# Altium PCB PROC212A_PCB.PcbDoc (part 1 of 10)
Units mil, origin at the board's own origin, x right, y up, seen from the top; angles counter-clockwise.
Board outline 3032.48 x 3598.78 mil, 4 copper layers (Top Layer, L2_GND1, L3_PWR1, Bottom Layer), stack 60.58 mil thick; 432 components, 310 nets, 7775 pads, 1236 vias.
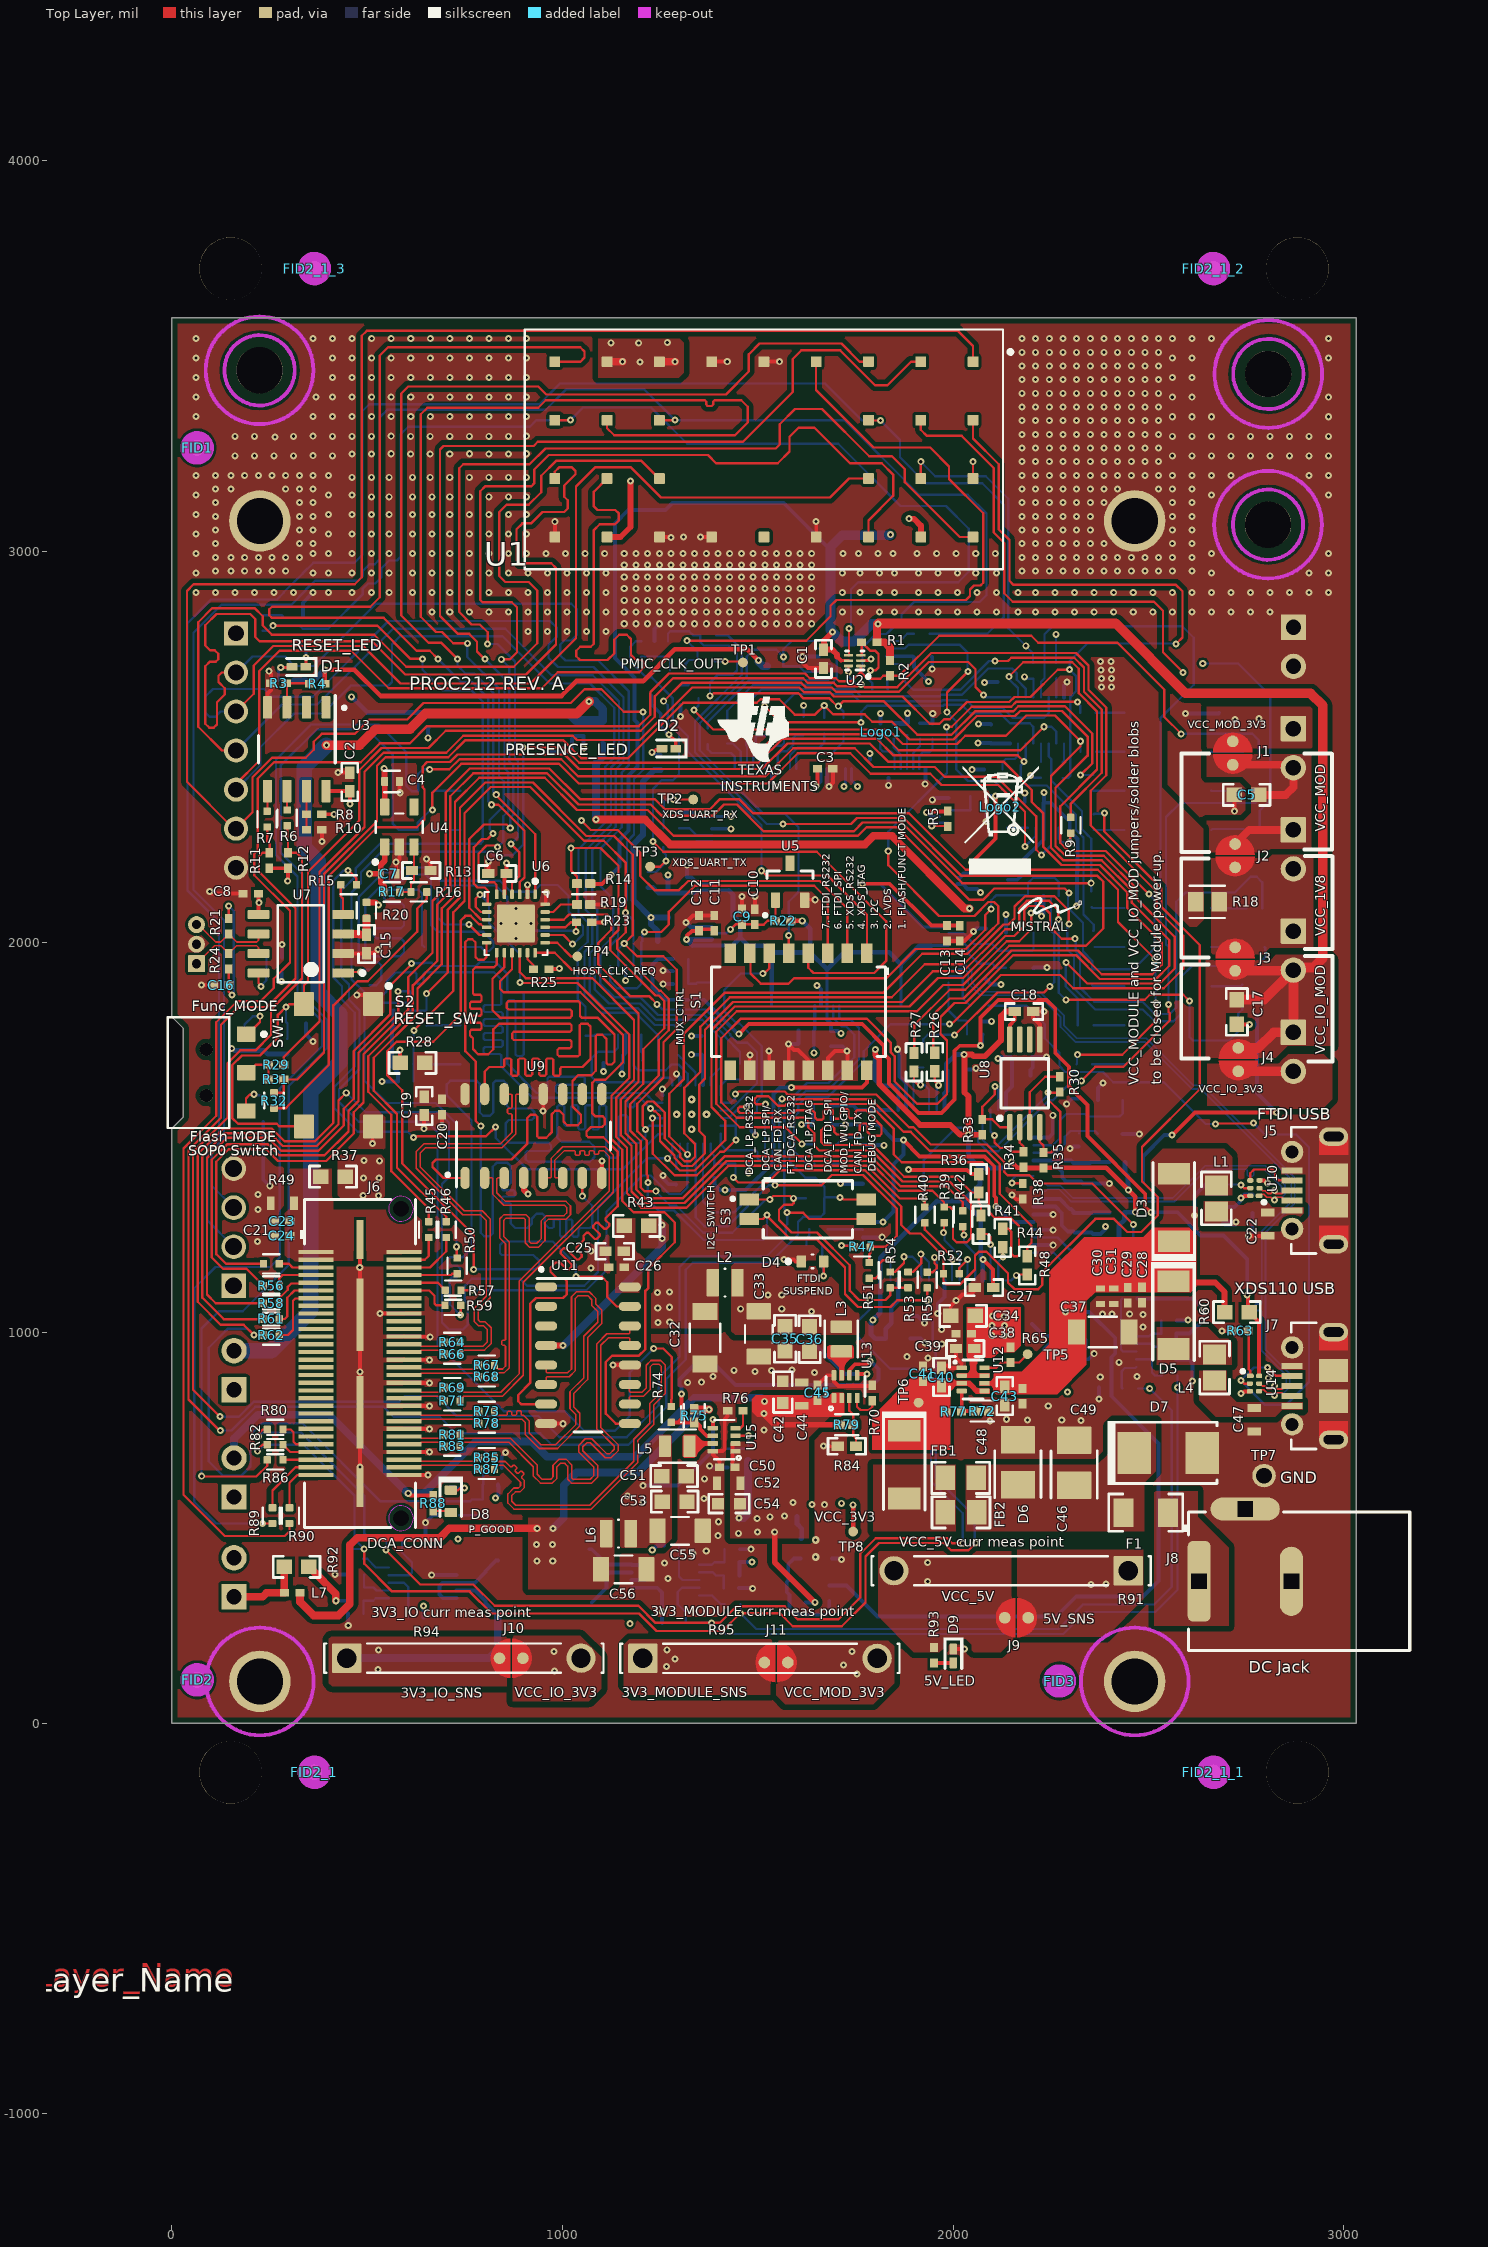
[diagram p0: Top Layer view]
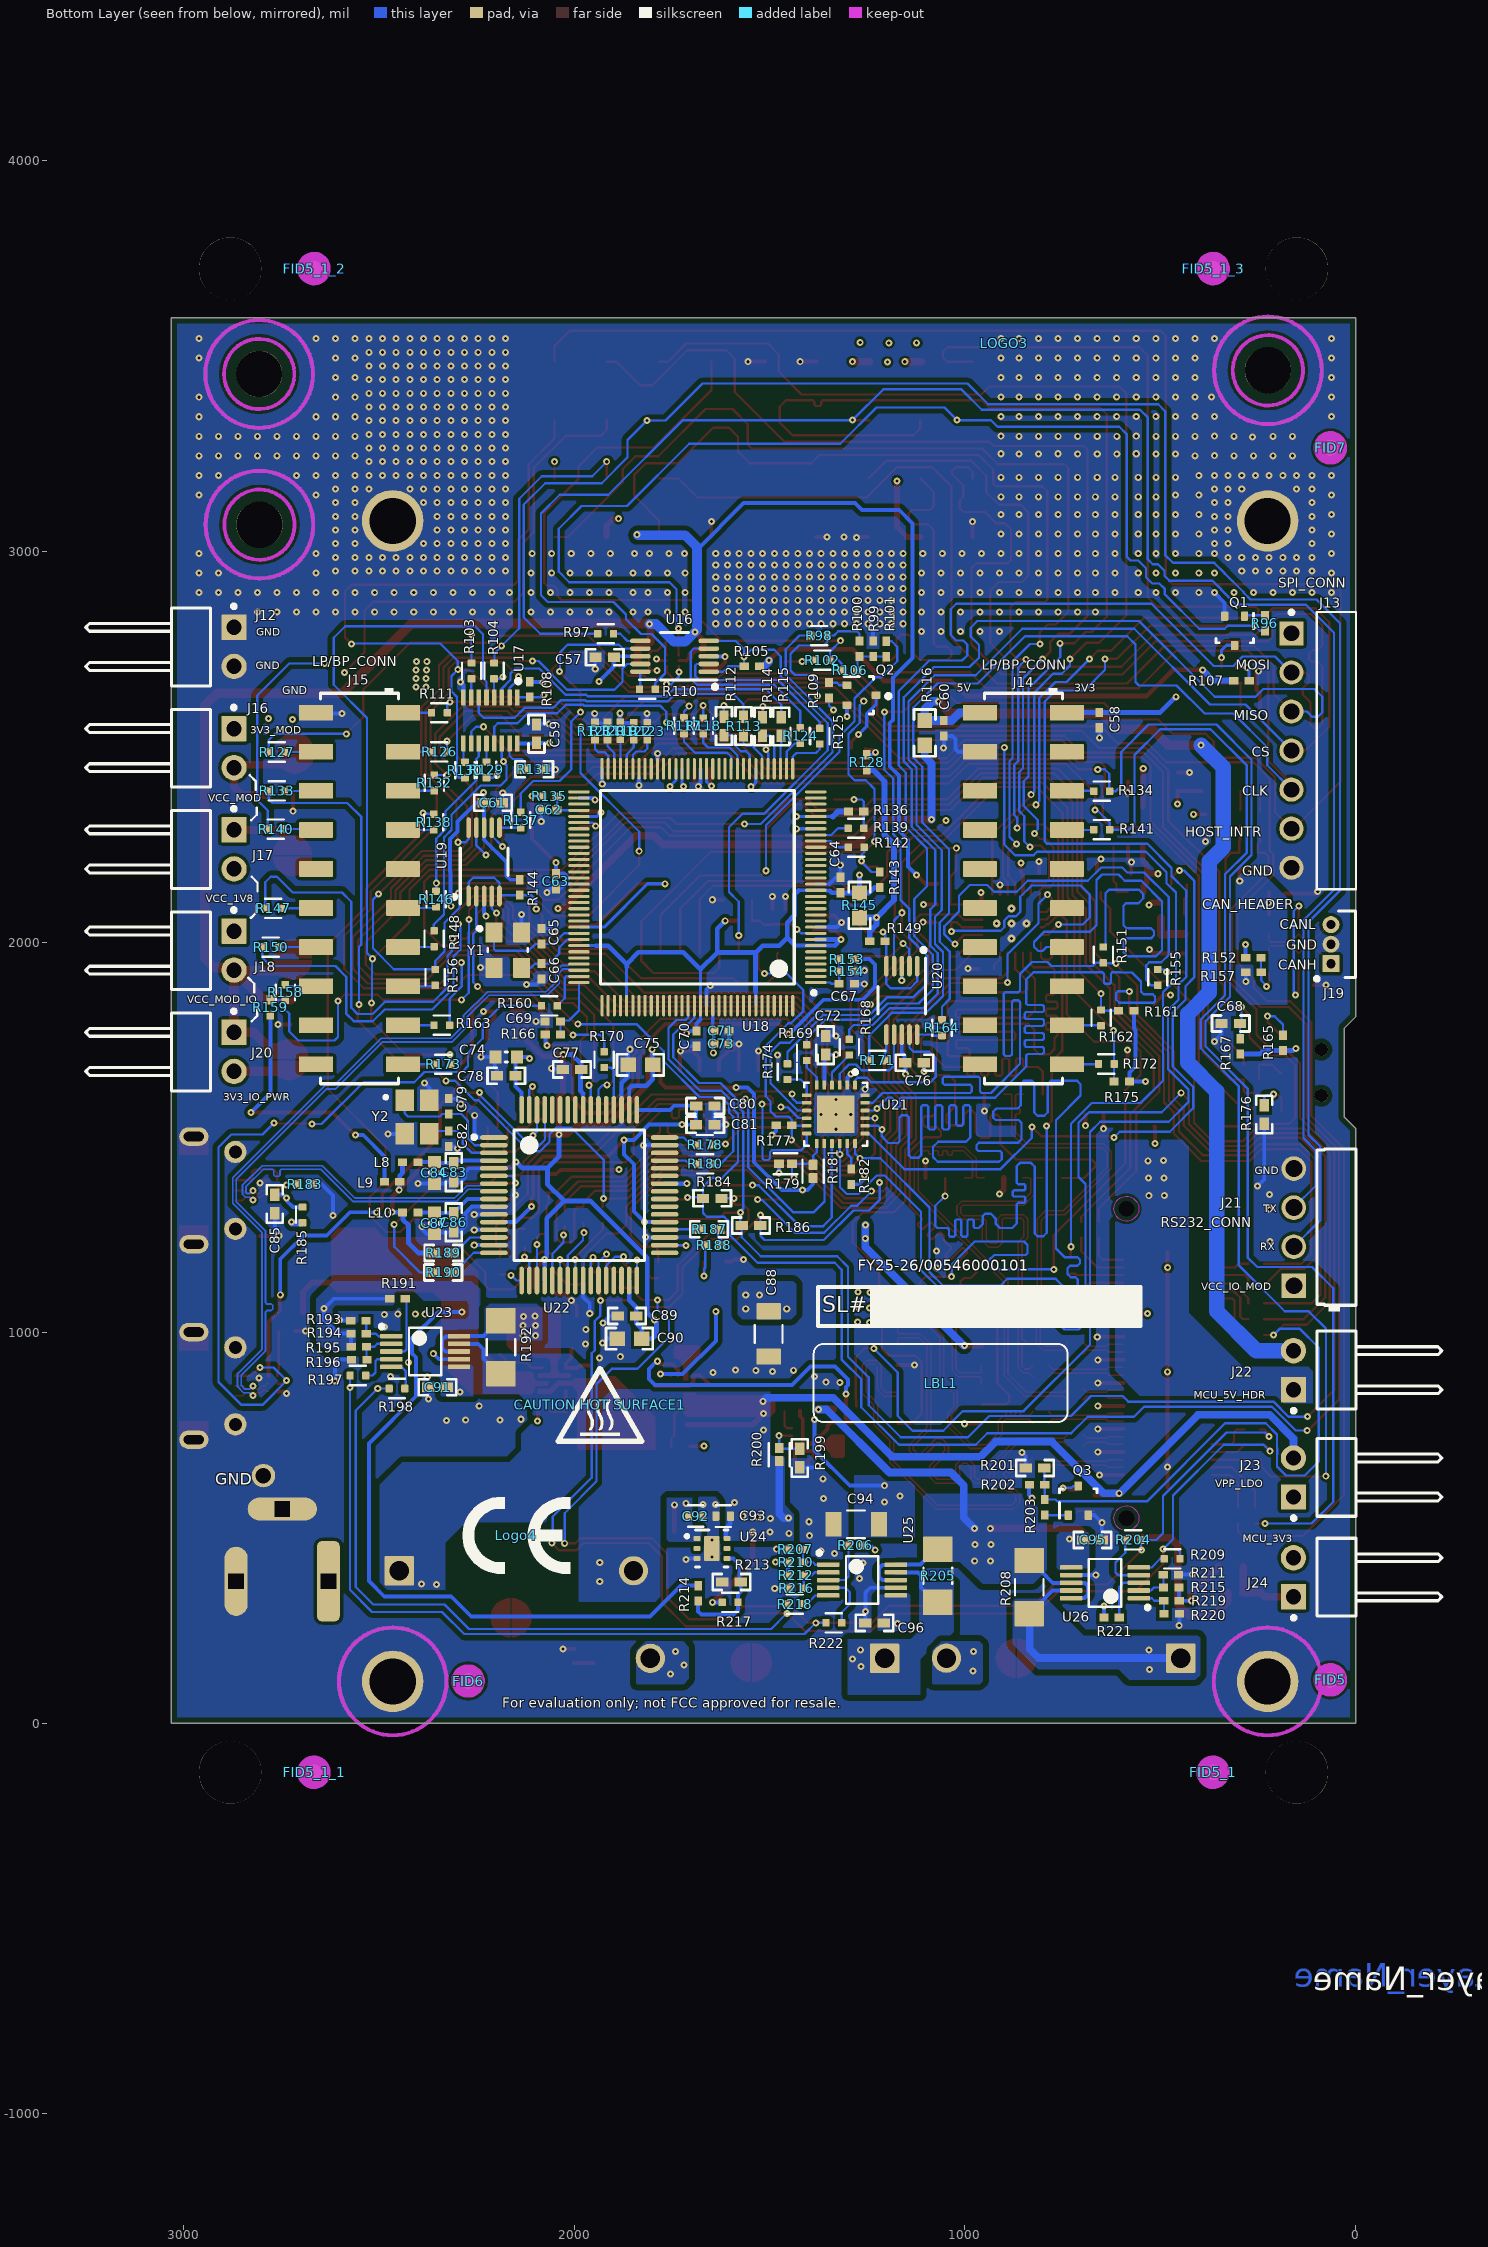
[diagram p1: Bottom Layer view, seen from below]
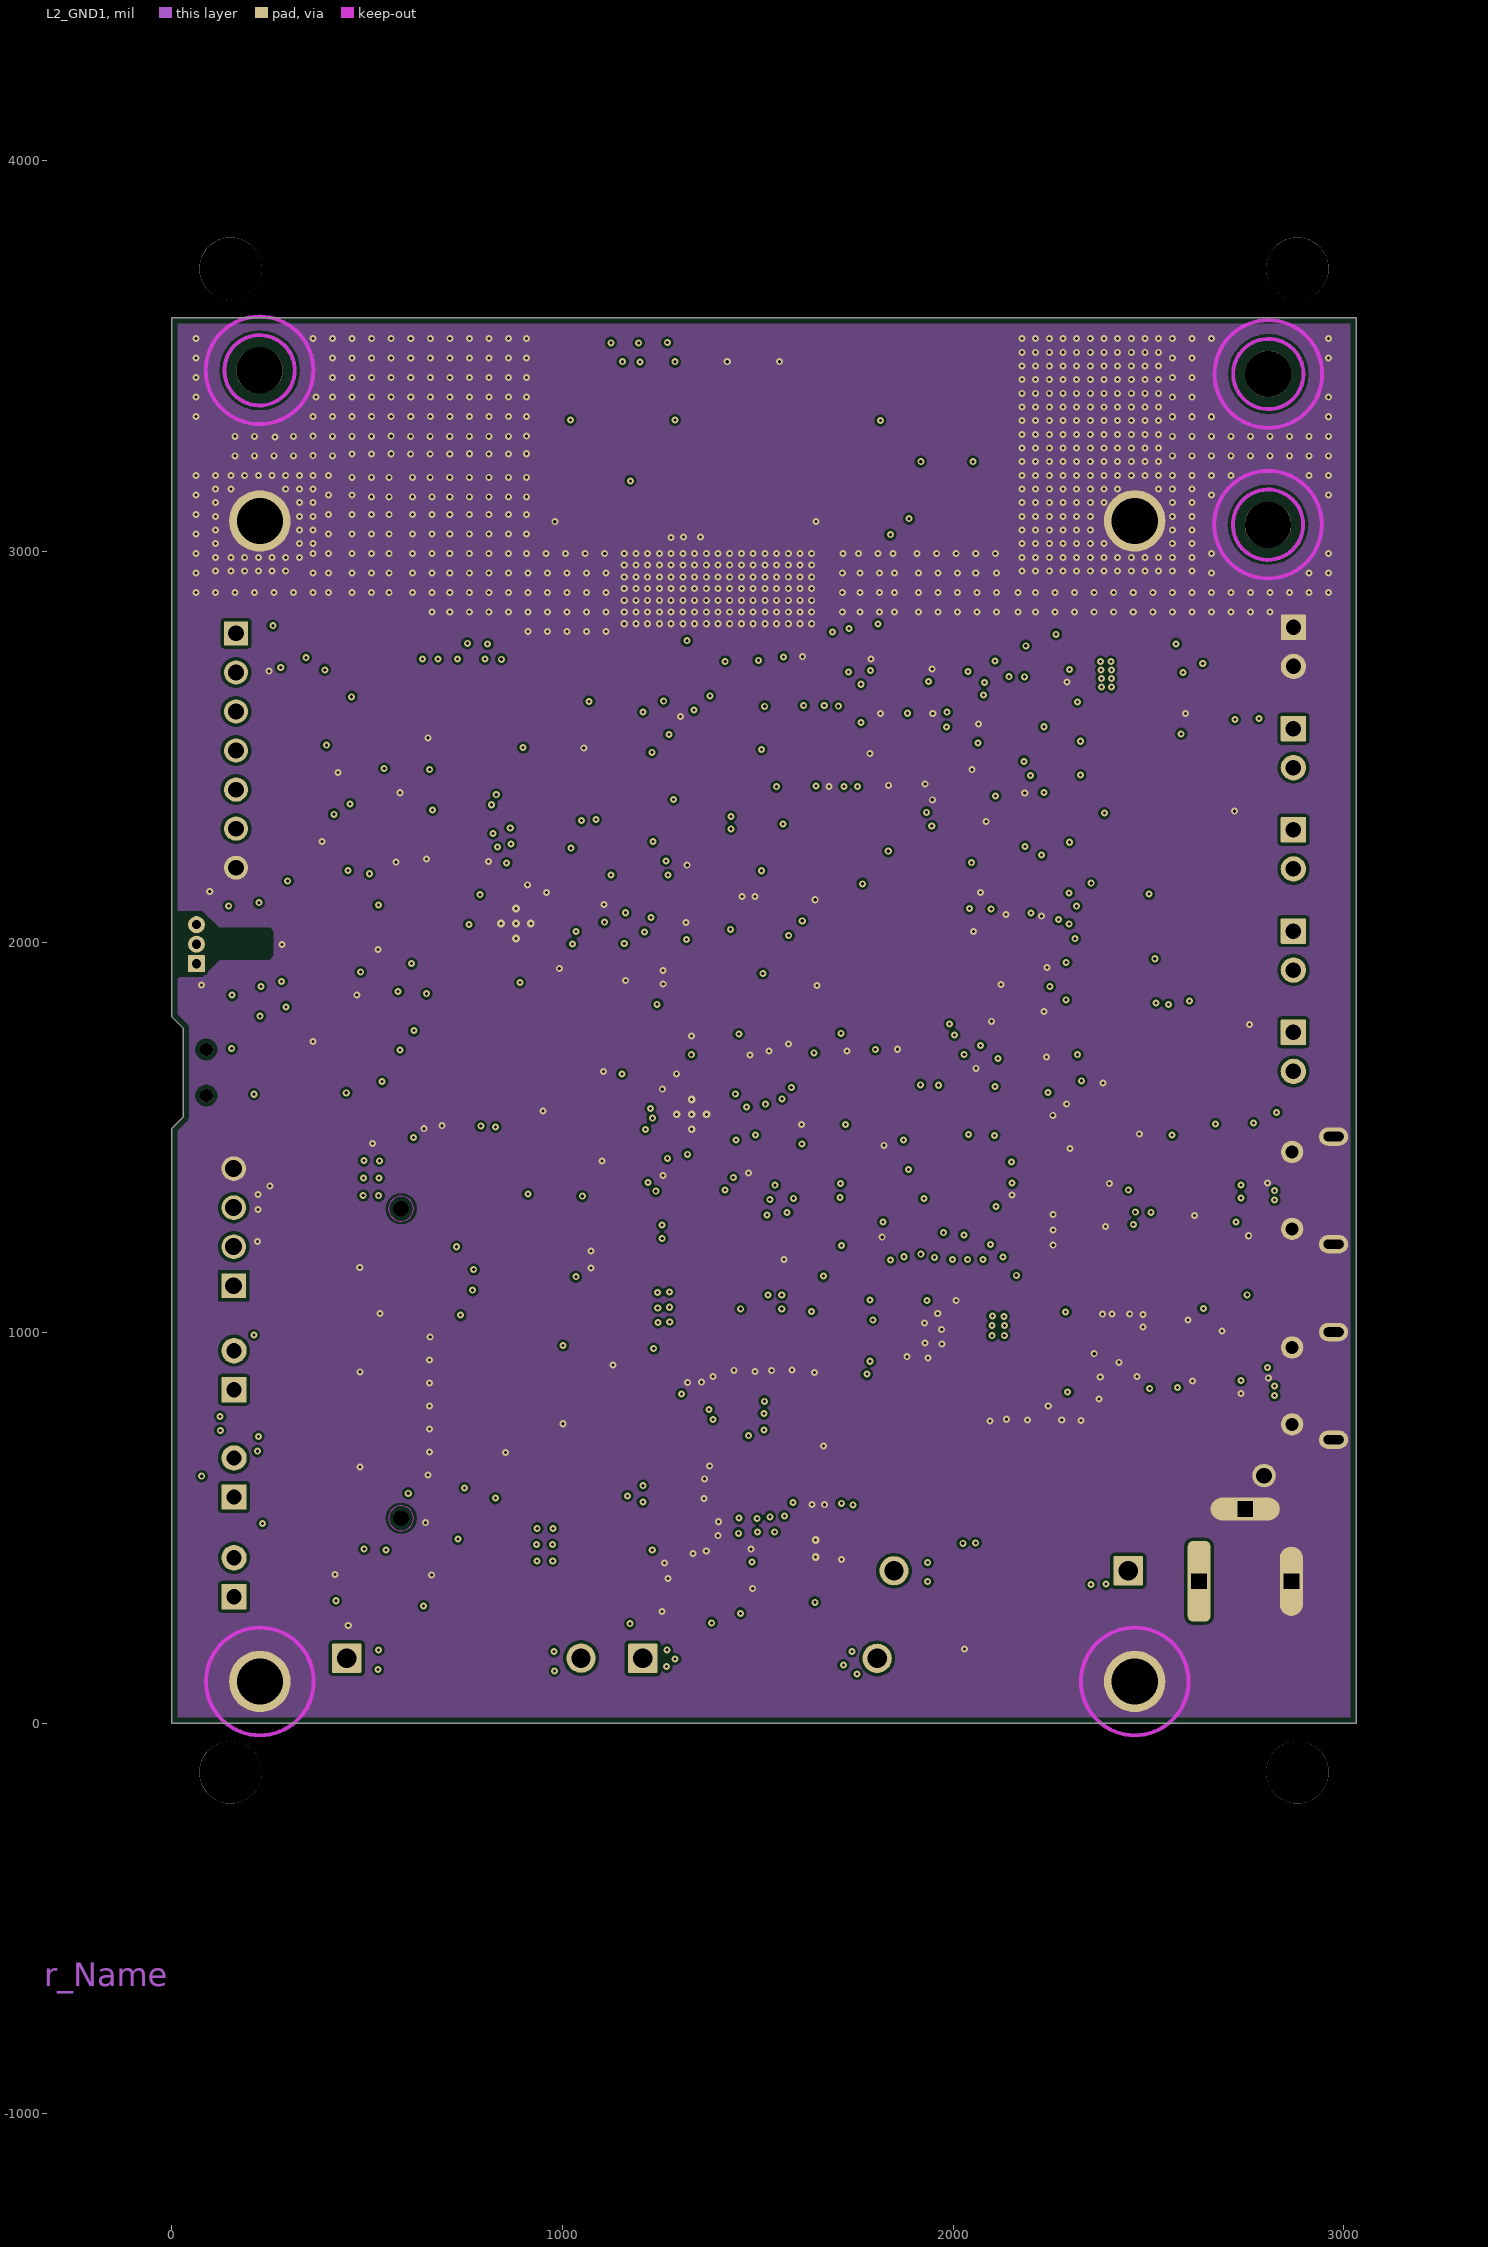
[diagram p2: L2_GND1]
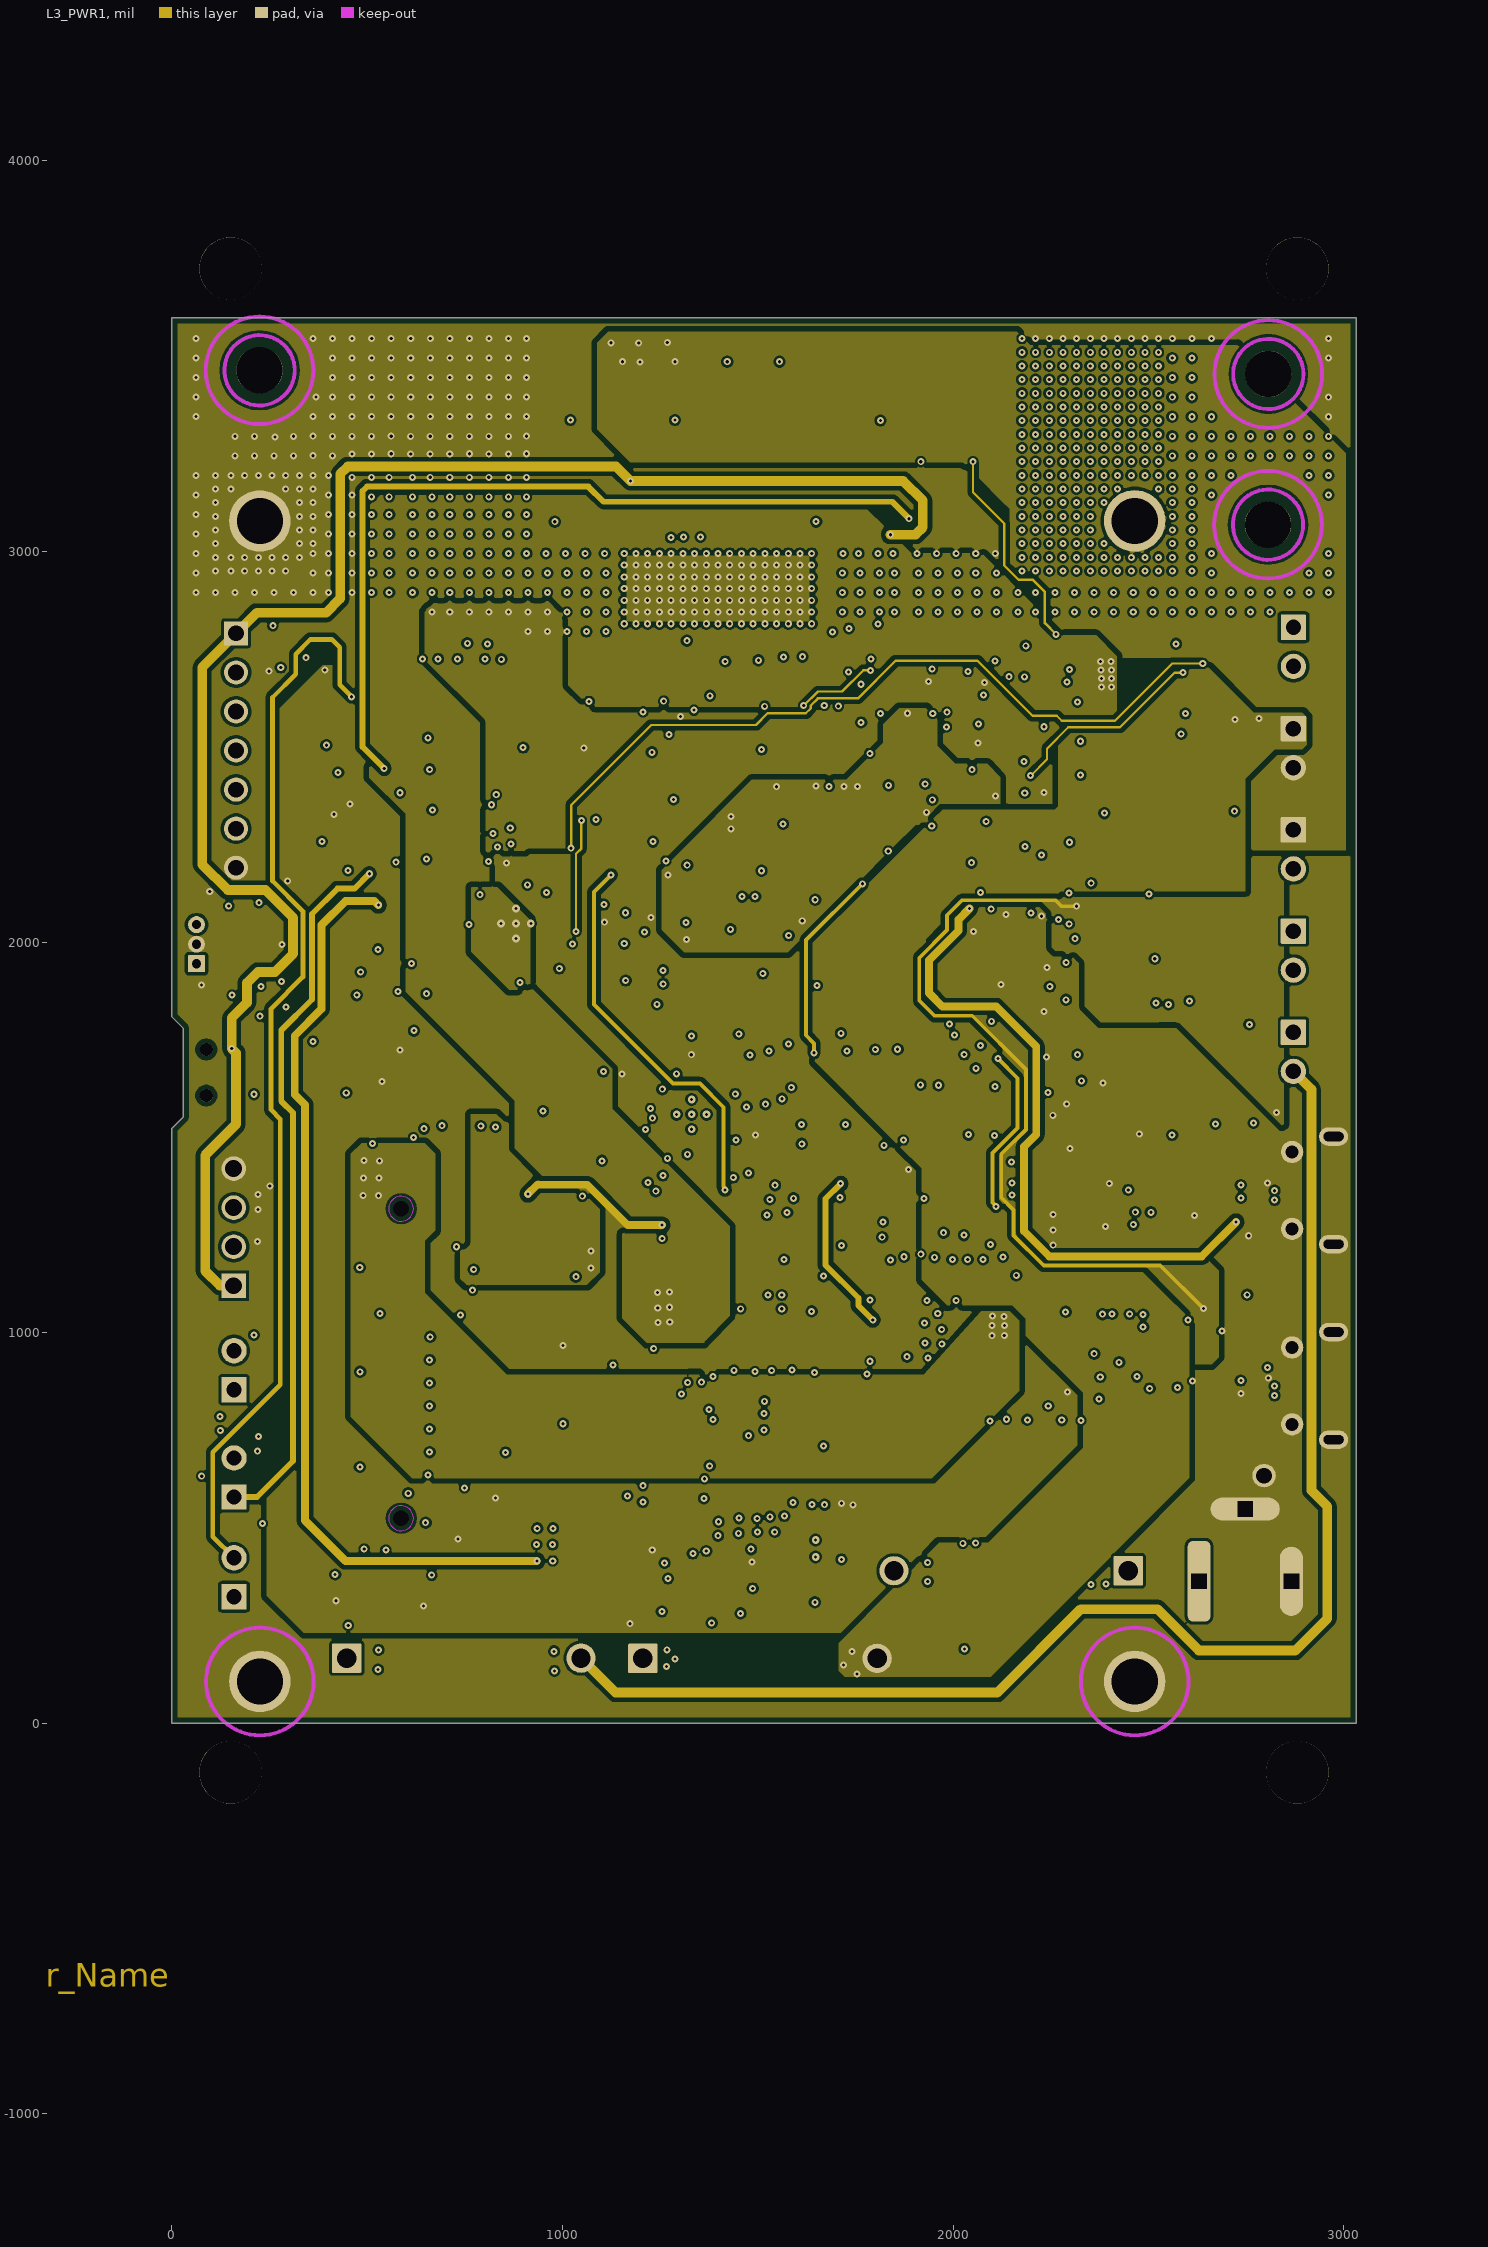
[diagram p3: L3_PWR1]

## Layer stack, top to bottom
Top Solder: solder mask 1, Solder Resist, Dk 3.5
Top Layer: signal copper 1.85
Dielectric 1: prepreg 1.779, Iteq IT180A Prepreg 106 RC71-NEW, Dk 3.79
Dielectric 2: prepreg 1.779, Iteq IT180A Prepreg 106 RC71-NEW, Dk 3.79
L2_GND1: signal copper 1.26
Dielectric 3: core 47.244, Iteq IT180A 50 mil core 1/1, Dk 4.28
L3_PWR1: signal copper 1.26
Dielectric 4: prepreg 1.779, Iteq IT180A Prepreg 106 RC71-NEW, Dk 3.79
Dielectric 5: prepreg 1.779, Iteq IT180A Prepreg 106 RC71-NEW, Dk 3.79
Bottom Layer: signal copper 1.85
Bottom Solder: solder mask 1, Solder Resist, Dk 3.5

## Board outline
0,0 0,1523.4 29.41,1552.81 29.41,1779.02 0,1808.43 0,3598.78 3031.47,3598.78 3032.48,3598.78 3032.48,0

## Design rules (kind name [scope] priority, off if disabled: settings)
AcuteAngle [All] p1 off: minimum=4.50000000000000E+0001 checktracksonly=FALSE
AssemblyTestPointUsage [All] p1: valid=2
BoardOutlineClearance BoardOutlineClearance_Silkoultine [OnBottomSilkscreen] p1: gap=12 ignorepadtopadclearanceinfootprint=FALSE except(0: Track-OutlineEdge Text-OutlineEdge; 15: Poly-OutlineEdge)
BoardOutlineClearance BoardOutlineClearance_J8 [InComponent('J8')] p2: gap=12 ignorepadtopadclearanceinfootprint=FALSE except(0: Track-OutlineEdge Text-OutlineEdge)
BoardOutlineClearance BoardOutlineClearance_SW1 [InComponent('SW1')] p3: gap=12 ignorepadtopadclearanceinfootprint=FALSE except(0: Track-OutlineEdge Text-OutlineEdge)
BoardOutlineClearance BoardOutlineClearance_Text [OnBottomSilkscreen] p4: gap=12 ignorepadtopadclearanceinfootprint=FALSE except(0: Track-OutlineEdge Text-OutlineEdge)
BoardOutlineClearance [All] p5: gap=12 ignorepadtopadclearanceinfootprint=FALSE except(15: Poly-OutlineEdge)
Clearance SOLDER_JUMPER [HasFootprint('SolderJumper')] p1: gap=6 ignorepadtopadclearanceinfootprint=TRUE except(0: Text-Hole; 4.8: SMDPad-Region Region-Region; 5: Arc-Arc Arc-Track Arc-SMDPad Track-SMDPad; 5.1: SMDPad-SMDPad; 7: Arc-Fill Arc-Poly Arc-Region Track-Fill Track-Region Poly-Region; 8: SMDPad-Fill SMDPad-Poly THPad-Fill THPad-Poly THPad-Region; 10: Fill-Fill Fill-Poly Fill-Region; 11: Fill-Hole Poly-Hole Region-Hole; 12: Track-Poly; 15: Poly-Poly)
Clearance 120E_Clearance [InNetClass('120E')] p2: gap=6 ignorepadtopadclearanceinfootprint=TRUE except(0: Text-Hole; 5: Arc-Arc Arc-Track Arc-SMDPad Track-SMDPad; 5.1: Track-Track SMDPad-SMDPad; 7: Arc-Fill Arc-Poly Arc-Region Track-Region SMDPad-Region; 8: SMDPad-Fill SMDPad-Poly THPad-Fill THPad-Poly THPad-Region; 10: Fill-Fill Fill-Poly Fill-Region Poly-Region Region-Region; 11: Fill-Hole Poly-Hole Region-Hole; 12: Track-Fill Track-Poly; 15: Poly-Poly)
Clearance 90E_1 [InNetClass('90E')] p3: gap=6 ignorepadtopadclearanceinfootprint=TRUE except(0: Text-Hole; 4.5: Track-Track Track-Via; 5: Arc-Arc Arc-Track Arc-SMDPad Track-SMDPad; 5.1: SMDPad-SMDPad; 7: Arc-Fill Arc-Poly Arc-Region Track-Fill Track-Region SMDPad-Region; 8: SMDPad-Fill SMDPad-Poly THPad-Fill THPad-Poly THPad-Region; 10: Fill-Fill Fill-Poly Fill-Region Poly-Region Region-Region; 11: Fill-Hole Poly-Hole Region-Hole; 12: Track-Poly; 15: Poly-Poly)
Clearance [All] p4: gap=6 ignorepadtopadclearanceinfootprint=TRUE except(0: Text-Hole; 5: Arc-Arc Arc-Track Arc-SMDPad Track-SMDPad; 5.1: SMDPad-SMDPad; 7: Arc-Fill Arc-Poly Arc-Region Track-Fill Track-Region SMDPad-Region Region-Region; 8: SMDPad-Fill SMDPad-Poly THPad-Fill THPad-Poly THPad-Region; 10: Fill-Fill Fill-Poly Fill-Region Poly-Region; 11: Fill-Hole Poly-Hole Region-Hole; 12: Track-Poly; 15: Poly-Poly)
Clearance Clearance_Keepout [IsKeepOut] p5: gap=0 ignorepadtopadclearanceinfootprint=TRUE
Clearance Clearance_BGA [WithinRoom('BGA1')] p6: gap=4 ignorepadtopadclearanceinfootprint=FALSE except(8: Fill-Fill Fill-Poly Fill-Region Poly-Poly Poly-Region Region-Region; 10: Fill-Hole Poly-Hole Region-Hole)
Clearance "top and bottom" [OnTopLayer or OnBottomLayer] p7: gap=6 ignorepadtopadclearanceinfootprint=TRUE except(5: Arc-Arc Arc-Track Arc-SMDPad Arc-Hole Track-Track Track-SMDPad Track-Hole SMDPad-Hole THPad-Hole Via-Hole Text-Hole; 5.1: SMDPad-SMDPad; 7: Arc-Fill Arc-Poly Arc-Region Track-Fill Track-Region; 8: Track-Poly SMDPad-Fill SMDPad-Poly SMDPad-Region THPad-Fill THPad-Poly THPad-Region Via-Fill Via-Poly Via-Region Poly-Poly; 10: Fill-Fill Fill-Poly Fill-Region Poly-Region Region-Region; 11: Fill-Hole Poly-Hole Region-Hole)
Clearance "Inner layers" [OnLayer('L3_SIGNAL 1') OR ('L6_SIGNAL 4')] p8: gap=6 ignorepadtopadclearanceinfootprint=TRUE except(0: Text-Hole; 5: Arc-Arc Arc-Track Arc-SMDPad Track-SMDPad; 5.1: SMDPad-SMDPad; 7: Arc-Fill Arc-Poly Arc-Region Track-Fill Track-Region; 8: SMDPad-Fill SMDPad-Poly SMDPad-Region THPad-Fill THPad-Poly THPad-Region; 10: Fill-Fill Fill-Poly Fill-Region Poly-Region Region-Region; 11: Fill-Hole Poly-Hole Region-Hole; 15: Track-Poly; 20: Poly-Poly)
Clearance Same_net [All] p9: gap=0 ignorepadtopadclearanceinfootprint=TRUE
Clearance Fiducial [HasFootprint('Fiducial10-20')] p10: gap=0 ignorepadtopadclearanceinfootprint=TRUE
ComponentClearance ComponentClearance_MatingCon-3D [All vs InComponentClass('Header')] p1: gap=0 collisioncheckmode=3 verticalgap=100 showdistances=FALSE
ComponentClearance "ComponentClearance_WEE Logo" [InComponent('Logo4')] p2: gap=0 collisioncheckmode=3 verticalgap=0 showdistances=TRUE
ComponentClearance ComponentClearance_Logo [InComponentClass('Logo')] p3: gap=0 collisioncheckmode=3 verticalgap=0 showdistances=TRUE
ComponentClearance "ComponentClearance_Mounting Holes_Fiducial Marks" [InComponentClass('FiducialMark') vs InPadClass('Mounting Holes PADS')] p4: gap=50 collisioncheckmode=3 verticalgap=10 showdistances=TRUE
ComponentClearance [All] p5: gap=6 collisioncheckmode=3 verticalgap=10 showdistances=TRUE
DiffPairsRouting 90E [InDifferentialPairClass('90E')] p1: maxlimit=4.5 minlimit=4.5 mostfreqgap=4.5 toplayer_minwidth=4.5 toplayer_maxwidth=4.5 toplayer_prefwidth=4.5 midlayer1_minwidth=4.5 midlayer1_maxwidth=4.5 midlayer1_prefwidth=4.5 midlayer5_minwidth=4.5 midlayer5_maxwidth=4.5 midlayer5_prefwidth=4.5 bottomlayer_minwidth=4.5 bottomlayer_maxwidth=4.5 bottomlayer_prefwidth=4.5 maxuncoupledlength=500
DiffPairsRouting 100E [InDifferentialPairClass('100E')] p2: maxlimit=6 minlimit=6 mostfreqgap=6 toplayer_minwidth=4 toplayer_maxwidth=4 toplayer_prefwidth=4 midlayer1_minwidth=4 midlayer1_maxwidth=4 midlayer1_prefwidth=4 midlayer5_minwidth=4 midlayer5_maxwidth=4 midlayer5_prefwidth=4 bottomlayer_minwidth=4 bottomlayer_maxwidth=4 bottomlayer_prefwidth=4 maxuncoupledlength=500
DiffPairsRouting 120E [InDifferentialPair('CAN')] p3: maxlimit=5.1 minlimit=5.1 mostfreqgap=5.1 toplayer_minwidth=4 toplayer_maxwidth=4 toplayer_prefwidth=4 midlayer1_minwidth=4 midlayer1_maxwidth=4 midlayer1_prefwidth=4 midlayer5_minwidth=4 midlayer5_maxwidth=4 midlayer5_prefwidth=4 bottomlayer_minwidth=4 bottomlayer_maxwidth=4 bottomlayer_prefwidth=4 maxuncoupledlength=500
FabricationTestPointUsage TestPointUsage [All] p1: valid=2 allowmultiple=FALSE
FabricationTestpoint Testpoint [All] p1: side=3 testpointundercomponent=TRUE minsize=40 maxsize=100 preferedsize=60 minholesize=0 maxholesize=40 preferedholesize=32 testpointgrid=1 allowsidetop=TRUE allowsidebottom=TRUE usegrid=TRUE gridtolerance=0.01
FanoutControl Fanout_LCC [IsLCC] p1: bgadir=Out bgaviamode=Centered fanoutstyle=Auto fanoutdirection=Alternating viagrid=1 // Fanout_LCC (Default Rule)
FanoutControl Fanout_BGA [IsBGA] p2: bgadir=Out bgaviamode=Centered fanoutstyle=Auto fanoutdirection=Alternating viagrid=1 // Fanout_BGA (Default Rule)
FanoutControl Fanout_Default [All] p4: bgadir=Out bgaviamode=Centered fanoutstyle=Auto fanoutdirection=Alternating viagrid=1 // Fanout_Default (Default Rule)
FanoutControl Fanout_Small [(CompPinCount < 5)] p5: bgadir=Out bgaviamode=Centered fanoutstyle=Auto fanoutdirection=OutThenIn viagrid=1 // Fanout_Small (Default Rule)
Height Room_Hieght [WithinRoom('Room_Hieght 1 MM')] p1: minheight=0 maxheight=41.34 prefheight=39.37
HoleSize [All] p1: absolutevalues=TRUE maxlimit=280 minlimit=5.9 maxpercent=80.000 minpercent=20.000
HoleToHoleClearance HoleToHoleClearance_1 [WithinRoom('BGA1')] p1: gap=4 allowstackedmicrovias=FALSE
MatchedLengths LVDS_100E_phase-match [InNetClass('100E')] p1: tolerance=1.5 checknetsindiffpair=TRUE checkdiffpairvsdiffpair=FALSE checkxsignals=FALSE checkothers=FALSE
MatchedLengths LVDS_DATA [InNetClass('LVDS_DATA')] p2: tolerance=1.25 checknetsindiffpair=FALSE checkdiffpairvsdiffpair=TRUE checkxsignals=TRUE checkothers=TRUE
MatchedLengths FTDI_SPI [InxSignalClass('FTDI_SPI')] p3: tolerance=50 checknetsindiffpair=FALSE checkdiffpairvsdiffpair=TRUE checkxsignals=TRUE checkothers=TRUE
MatchedLengths DCA_SPI_J6 [InxSignalClass('DCA_SPI_J6')] p4: tolerance=50 checknetsindiffpair=FALSE checkdiffpairvsdiffpair=TRUE checkxsignals=TRUE checkothers=TRUE targetsourcename=DCA_LP_SPI_CLK-DCA_SPI_CLK_PP1
MatchedLengths LPBP_SPI [InxSignalClass('LPBP_SPI')] p5: tolerance=100 checknetsindiffpair=FALSE checkdiffpairvsdiffpair=TRUE checkxsignals=TRUE checkothers=TRUE
MatchedLengths SPI_HED-MUX [InxSignalClass('SPI_HED-MUX')] p6: tolerance=50 checknetsindiffpair=FALSE checkdiffpairvsdiffpair=TRUE checkxsignals=TRUE checkothers=TRUE
MatchedLengths SPI_MOD-HED [InxSignalClass('SPI_MOD-HED')] p7: tolerance=50 checknetsindiffpair=FALSE checkdiffpairvsdiffpair=TRUE checkxsignals=TRUE checkothers=TRUE
MatchedLengths LVDS_SIGNAL_50E [InNetClass('LVDS_SIGNAL_50E')] p8: tolerance=1.25 checknetsindiffpair=FALSE checkdiffpairvsdiffpair=TRUE checkxsignals=TRUE checkothers=TRUE
MatchedLengths 90E_phase-match_1 [InNetClass('90E')] p9: tolerance=1.5 checknetsindiffpair=TRUE checkdiffpairvsdiffpair=FALSE checkxsignals=FALSE checkothers=FALSE
MatchedLengths LVDS_100E [InxSignalClass('LVDS_100E')] p10: tolerance=1.5 checknetsindiffpair=FALSE checkdiffpairvsdiffpair=TRUE checkxsignals=TRUE checkothers=TRUE
MinimumAnnularRing MinimumAnnularRing_ThermalPadVias [IsVia and InAnyComponent] p1: minimumring=3.9
MinimumAnnularRing [All] p2: minimumring=3.9
MinimumSolderMaskSliver MinimumSolderMaskSliver_Logo [InComponentClass('Logo') vs InComponentClass('Logo')] p1: minsoldermaskwidth=0.7
MinimumSolderMaskSliver [All] p2: minsoldermaskwidth=3.5
PlaneConnect [All] p1: planeconnectstyle=Relief reliefexpansion=10 reliefentries=4 reliefconductorwidth=10 reliefairgap=10
PolygonConnect [All] p1: connectstyle=Direct reliefconductorwidth=10 reliefentries=4 polygonreliefangle="90 Angle" airgapwidth=10
RoutingVias ThermalPadVias [IsVia and InAnyComponent] p1: holewidth=7.87 width=19.68 viastyle="Through Hole" minholewidth=5 minwidth=13 maxholewidth=12.99 maxwidth=23.62
RoutingVias [All] p2: holewidth=12.2 width=22.4 viastyle="Through Hole" minholewidth=5.9 minwidth=14 maxholewidth=20 maxwidth=40
SMDToCorner [All] p1: distance=25000
SilkToBoardRegionClearance [Not ((IsComment or IsDesignator) And (Hide <> 'False')) and not InRegion(1000,500,4000,800)] p1:
SilkToSilkClearance [All] p1: silktosilkclearance=3
SilkToSolderMaskClearance SilkToSolderMaskClearance_OutLine [istrack and InAnyComponent] p1: minsilkscreentomaskgap=0 clearancetoexposedcopper=FALSE
SilkToSolderMaskClearance SilkscreenOverComponentPads [IsPad] p2: minsilkscreentomaskgap=3 clearancetoexposedcopper=FALSE
SolderMaskExpansion [All] p1: expansion=0 istentingtop=FALSE
UnRoutedNet [All] p1: checkbadconnections=TRUE
Width power [InNetClass('POWER')] p1: maxlimit=100 minlimit=8 preferedwidth=8 minimp=50.000000 maximp=50.000000 favimp=50.000000
Width DEFAULT [All] p2: maxlimit=30 minlimit=5.9 preferedwidth=5.9 minimp=50.000000 maximp=50.000000 favimp=50.000000
12 further rules are at their usual default settings.

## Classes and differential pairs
component class PROC212A_Reset_SW_LED_&_PRESENCE_LED: C1 C68 D1 D2 Q1 Q2 R1 R2 R96 R107 R109 R128 R167 S2 U2
net class 120E: CANH CANL
net class 90E: FTDI_USBD_N FTDI_USBD_P XDSET_1_DM XDSET_1_DP
net class 100E: RADAR_LVDS_0M RADAR_LVDS_0P RADAR_LVDS_1M RADAR_LVDS_1P RADAR_LVDS_2M RADAR_LVDS_2P RADAR_LVDS_3M RADAR_LVDS_3P RADAR_LVDS_CLKM RADAR_LVDS_CLKP RADAR_LVDS_FRCLKM RADAR_LVDS_FRCLKP
net class LVDS_DATA: RADAR_LVDS_CLK RADAR_LVDS_DATA0 RADAR_LVDS_DATA1 RADAR_LVDS_DATA2 RADAR_LVDS_DATA3 RADAR_LVDS_FRCLK
net class 50E: DCA_LP_SPI_CLK DCA_LP_SPI_CS DCA_LP_SPI_MISO DCA_LP_SPI_MOSI FTDI_SPI_CLK FTDI_SPI_CS FTDI_SPI_MISO FTDI_SPI_MOSI LVDS_CLK_DC_PWM_AUTO_CTRL_GPIO LVDS_D0_MODULE_WAKEUP_GPIO_2 LVDS_D1_CAN_FD_RX_SPI_RS232_CTRL_GPIO_3 LVDS_D2_CAN_FD_TX LVDS_D3_PRESENCE_INDICATION_GPIO LVDS_FRCLK_HOST_CLK_REQ MUX_SPI_CLK_I2C_SCL MUX_SPI_CS_I2C_SDA MUX_SPI_MISO MUX_SPI_MOSI RADAR_LVDS_CLK RADAR_LVDS_DATA0 RADAR_LVDS_DATA1 RADAR_LVDS_DATA2 RADAR_LVDS_DATA3 RADAR_LVDS_FRCLK RS232_FTDI_RX RS232_FTDI_TX SPI_CLK_I2C_SCL SPI_CS_I2C_SDA SPI_MISO SPI_MOSI TCK TDI TMS
differential pair class 100E: LVDS_0 LVDS_0_DP3 LVDS_1 LVDS_1_DP4 LVDS_2 LVDS_2_DP5 LVDS_3 LVDS_3_DP6 LVDS_CLK LVDS_CLK_DP7 LVDS_FRCLK LVDS_FRCLK_DP8
differential pair class 90E: FTDI_USB_SIGNAL FTDI_USBD XDS_USB
net class LVDS_SIGNAL_50E: LVDS_CLK_DC_PWM_AUTO_CTRL_GPIO LVDS_D0_MODULE_WAKEUP_GPIO_2 LVDS_D1_CAN_FD_RX_SPI_RS232_CTRL_GPIO_3 LVDS_D2_CAN_FD_TX LVDS_D3_PRESENCE_INDICATION_GPIO LVDS_FRCLK_HOST_CLK_REQ
component class "PROC212A_ANALOG_JTAG_MUX, CAN & SOP_CTRL": C8 C15 C16 C59 D10 J19 Q5 R15 R20 R21 R24 R29 R31 R32 R98 R99 R100 R101 R102 R103 R104 R106 R108 R129 R130 R131 R152 R155 R157 R165 R176 R234 S1 SW1 TP1 U7 U17
component class PROC212A_Current_sensors_EPROM: C2 C91 C95 C96 C138 C139 C140 C141 C142 C143 C144 C145 C146 C147 C148 C149 C150 C151 C152 C153 C157 C158 D10 J9 J10 J11 R3 R4 R6 R7 R8 R10 R11 R12 R91 R94 R95 R191 R192 R193 R194 R195 R196 R197 R198 R204 R205 R206 R207 R208 R209 R210 R211 R212 R215 R216 R218 R219 R220 R221 R222 R232 R237 R251 R252 R259 R260 U3 U23 U25 U26 U27 U29 Y3
component class PROC212A_BP_MMWAVE_MODULE: C5 C17 J1 J2 J3 J4 J12 J16 J17 J18 J20 J25 U1
net class POWER: 3V3_IO_SNS 3V3_LDO_EN 3V3_MODULE_SNS 5V_DC 5V_IN_USB 5V_JACK_IN 5V_SNS CONN_5V DC_JACK_5V FTDI_3V3 FTDI_VBUS FTDI_VCORE GND MCU_3V3 MCU_5V NetC15_2 NetC85_1 NetD2_2 NetD9_1 NetJ24_1 REG_1V8 REG_3V3 REG_OUT_1V8 REG_OUT_3V3 REG_PG SW_PR1 USB_5V USB_5V_D1 VCC_1V8 VCC_3V3 VCC_5V VCC_5V_IN VCC_IO_3V3 VCC_IO_MODULE VCC_MOD_3V3 VCC_MODULE VCC_XDS_3V3 VDD1_3V3 VDD2_3V3 VDDC_1 VPHY_FTDI VPLL_FTDI VPP_1P7 VPP_LDO_IN_5V XDSET_1_VBUS
component class PROC212A_DC_Regulators: C4 C7 C32 C33 C35 C36 C42 C44 C45 C50 C51 C52 C53 C54 C55 C56 C88 C92 C93 C94 C97 C98 C99 C102 C106 C107 C108 C113 C114 C115 C116 C118 C124 C125 C126 C127 J23 L2 L3 L5 L6 mm R13 R16 R17 R18 R70 R74 R75 R76 R79 R84 R145 R199 R200 R201 R202 R213 R214 R217 R231 R233 R234 R236 R239 R252 S5 TP7 TP8 TP11 U4 U13 U15 U24
component class PROC212A_DCA1000_LP_BP_Connectors: C21 C23 C24 C58 C60 C107 C114 C115 C139 C146 J6 J13 J14 J15 J21 J22 J24 L7 L13 R37 R45 R46 R49 R50 R56 R57 R58 R59 R61 R62 R64 R66 R67 R68 R69 R71 R73 R78 R80 R81 R82 R83 R85 R86 R87 R89 R90 R92 R111 R116 R126 R127 R132 R133 R134 R138 R140 R141 R146 R147 R148 R150 R151 R156 R158 R159 R161 R162 R163 R172 R173 R175 R232 R237 TP11
component class Logo: Logo1
component class FiducialMark: FID1 FID2 FID3 FID5 FID6 FID7
component class Label: LBL1
component class PROC212A_EVM_Hardware: "CAUTION HOT SURFACE1" FID1 FID2 FID3 FID5 FID6 FID7 LBL1 Logo1 Logo2 LOGO3 Logo4 ZZ1 ZZ2 ZZ3 ZZ4 ZZ5
component class PROC212A_ANALOG_MUX_SPI: C57 C61 C72 C76 R9 R97 R105 R110 R137 R144 R149 R164 R168 R169 R171 R174 R177 R182 R239 U16 U19 U20 U21
component class PROC212A_ANALOG_MUX_LVDS_DRIVER: C6 C19 C20 C25 C26 C139 C145 C152 R14 R19 R23 R25 R28 R43 R179 R181 TP4 U6 U9 U11
component class PROC212A_XDS110_Interface: C3 C9 C10 C11 C12 C13 C14 C62 C63 C64 C65 C66 C67 C69 C70 C71 C73 R5 R22 R112 R113 R114 R115 R117 R118 R119 R120 R121 R122 R123 R124 R125 R135 R136 R139 R142 R143 R153 R154 R160 R166 R184 R186 R234 S3 TP2 TP3 U5 U18 Y1
component class AssemblyNote: ZZ1 ZZ2 ZZ3 ZZ4 ZZ5
component class PROC212A_USB_DC_JACK_PWR_Switch: C28 C29 C30 C31 C34 C37 C38 C39 C40 C41 C43 C46 C47 C48 C49 C134 C135 C136 C137 C141 C158 D3 D5 D6 D7 D8 D9 D10 F1 FB1 FB2 FL1 FL2 J7 J8 L1 L4 L13 LD1 Q3 Q5 R60 R63 R65 R72 R77 R88 R93 R203 TP5 TP6 TP11 TP12 U12 U14
component class PROC212A_FTDI: C18 C22 C27 C74 C75 C77 C78 C79 C80 C81 C82 C83 C84 C85 C86 C87 C89 C90 D4 J5 J25 L8 L9 L10 LD2 LD4 R26 R27 R30 R33 R34 R35 R36 R38 R39 R40 R41 R42 R44 R47 R48 R51 R52 R53 R54 R55 R170 R178 R180 R183 R185 R187 R188 R189 R190 R223 R224 R225 R226 R227 R228 R229 R230 R232 SW2 U8 U10 U22 Y2
component class Header: J21
differential pair FTDI_USB_SIGNAL: +FTDI_USBD_P -FTDI_USBD_N
differential pair CAN: +CANL -CANH
differential pair LVDS_FRCLK: +NetJ6_26 -NetJ6_28
differential pair LVDS_FRCLK_DP8: +RADAR_LVDS_FRCLKP -RADAR_LVDS_FRCLKM
differential pair LVDS_CLK: +NetJ6_46 -NetJ6_44
differential pair LVDS_CLK_DP7: +RADAR_LVDS_CLKP -RADAR_LVDS_CLKM
differential pair LVDS_3: +NetJ6_32 -NetJ6_34
differential pair LVDS_3_DP6: +RADAR_LVDS_3P -RADAR_LVDS_3M
differential pair LVDS_2: +NetJ6_38 -NetJ6_40
differential pair LVDS_2_DP5: +RADAR_LVDS_2P -RADAR_LVDS_2M
differential pair LVDS_1: +NetJ6_50 -NetJ6_52
differential pair LVDS_1_DP4: +RADAR_LVDS_1P -RADAR_LVDS_1M
differential pair LVDS_0: +NetJ6_56 -NetJ6_58
differential pair LVDS_0_DP3: +RADAR_LVDS_0P -RADAR_LVDS_0M
differential pair XDS_USB: +XDSET_1_DP -XDSET_1_DM

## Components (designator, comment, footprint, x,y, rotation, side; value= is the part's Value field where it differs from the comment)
C1 "GCM155R71H104KE02D" 0402 1668.49,2725.15 r90 top locked value=0.1uF
C2 "GCM155R71H104KE02D" 0402 455.06,2410.16 r90 top locked value=0.1uF
C3 "GRT155C81A105KE01D" 0402L 1672.41,2443.69 r0 top locked value=1uF
C4 "GRT155C71A225KE13D" FP-GRT155C71A225KE13D_0402-MFG 563.43,2411.48 r180 top locked value=2.2µF
C5 "GRM188Z71A106MA73D" 0603 2751.47,2376.89 r180 top locked value=10uF
C6 "GCM155R71H104KE02D" 0402 833.21,2175.81 r180 top value=0.1uF
C7 "GCM155C71A105KE38D" 0402_070 554.73,2175.11 r0 top locked value=1uF
C8 "C0402C104K8RACTU" 0402L 201.92,2124.03 r0 top locked value=0.1uF
C9 "GCM155R71E103KA37D" 0402L 1459.75,2064.98 r270 top locked value=0.01uF
C10 "C0402C104K8RACTU" 0402L 1492.61,2064.43 r270 top locked value=0.1uF
C11 "GRT155C81A105KE01D" 0402L 1388.42,2048.57 r90 top locked value=1uF
C12 "C0402C104K8RACTU" 0402L 1349.45,2048.57 r270 top locked value=0.1uF
C13 "C0402C104K8RACTU" 0402L 1984.32,2022.75 r90 top locked value=0.1uF
C14 "C1005X7S1A225K050BC" 0402_065L 2017.02,2022.43 r90 top locked value=2.2uF
C15 "GCM155R71H104KE02D" 0402 498.41,1995.26 r90 top locked value=0.1uF
C16 "GCM155R71H472KA37D" 0402L 126.14,1890.01 r0 top locked value=4700pF
C17 "GRM188Z71A106MA73D" 0603 2726.37,1821.23 r270 top locked value=10uF
C18 "GCM155R71H104KE02D" 0402 2181.46,1822.34 r0 top locked value=0.1uF
C19 "GCM155R71H104KE02D" 0402 645.75,1580.65 r270 top locked value=0.1uF
C20 "GCM155R71E103KA37D" 0402L 691.51,1577.81 r270 top locked value=0.01uF
C21 "GRT188R61A106KE13D" 0603S 282.81,1331.66 r0 top locked value=10uF
C22 "GRT188R61A106KE13D" 0603S 2805.53,1277.89 r90 top locked value=10uF
C23 "GRT155C81A105KE01D" 0402L 281.86,1285.5 r180 top locked value=1uF
C24 "GCM155C71A474KE36D" 0402L 281.7,1248.08 r180 top locked value=0.47uF
C25 "GCM155R71H104KE02D" 0402 1133.5,1208.71 r180 top locked value=0.1uF
C26 "GCM155R71E103KA37D" 0402L 1138.11,1167.21 r180 top locked value=0.01uF
C27 "GCM155R71H104KE02D" 0402 2079.07,1115.3 r180 top locked value=0.1uF
C28 "GCM155R71C224KE02D" 0402L 2483.62,1096.53 r90 top locked value=0.22uF
C29 "GCM155C71A474KE36D" 0402L 2446.93,1095.79 r270 top locked value=0.47uF
C30 "GRM155R61A106ME11D" 0402S 2377.61,1093.47 r270 top locked value=10uF
C31 "GRM155R61A106ME11D" 0402S 2411.66,1093.22 r90 top locked value=10uF
C32 "GRM31CR60J476ME19L" 1206_180 1364.73,986.79 r90 top locked value=47uF
C33 "GRM31CR70J226ME19K" FP-GRM31CR70J226ME19K_1206-MFG 1502.54,996.63 r90 top locked value=22µF
C34 "GRM188Z71A106MA73D" 0603 2025.59,1043.01 r180 top locked value=10uF
C35 "GRM188Z71A106MA73D" 0603 1569.79,984.37 r270 top locked value=10uF
C36 "GRM188Z71A106MA73D" 0603 1632.46,983.53 r270 top locked value=10uF
C37 "GRM31CR61A476KE15L" 1206_180 2383.14,1001.66 r0 top locked value=47uF
C38 "GRT155C81A105KE01D" 0402L 2027.3,997.1 r180 top locked value=1uF
C39 "GCM155R71H104KE02D" 0402 2030.93,959.66 r180 top locked value=0.1uF
C40 "GCM155R71H104KE02D" 0402 1970.08,886.4 r270 top locked value=0.1uF
C41 "GRT155C81A105KE01D" 0402L 1922.94,894.38 r90 top locked value=1uF
C42 "GRM188Z71A106MA73D" 0603_HV 1564.02,847.67 r90 top locked value=10uF
C43 "GCM155R71H104KE02D" 0402 2132.23,837.49 r90 top locked value=0.1uF
C44 "GRM188R71C474KA88D" 0603S 1612.8,842.66 r90 top locked value=0.47uF
C45 "GRM1555C1H471JA01D" 0402L 1653.1,846.5 r90 top locked value=470pF
C46 "GRT155C81A105KE01D" 0402L 2177.75,837.49 r270 top locked value=1uF
C47 "GRT188R61A106KE13D" 0603S 2771.31,777.09 r90 top value=10uF
C48 "T491B476K010AT" 3528-21 2166.02,667.91 r90 top locked value=47uF
C49 "T491B476K010AT" 3528-21 2310,666.71 r90 top locked value=47uF
C50 "GRM1555C1H471JA01D" 0402L 1421.93,655.05 r180 top locked value=470pF
C51 "GRM188Z71A106MA73D" 0603 1285.74,632.35 r0 top locked value=10uF
C52 "GRM188R71C474KA88D" 0603S 1425.83,614.28 r180 top locked value=0.47uF
C53 "GRM188Z71A106MA73D" 0603 1287.16,567.16 r0 top value=10uF
C54 "GRM188Z71A106MA73D" 0603_HV 1426.23,561.96 r180 top locked value=10uF
C55 "GRM31CR70J226ME19K" FP-GRM31CR70J226ME19K_1206-MFG 1301.07,492.66 r180 top locked value=22µF
C56 "GRM31CR70J226ME19K" FP-GRM31CR70J226ME19K_1206-MFG 1156.72,394.12 r180 top locked value=22µF
C57 "C0402C104K8RACTU" 0402 1922.36,2729.57 r0 bottom locked value=0.1uF
C58 "GCM155C71A474KE36D" 0402L 656.51,2568.34 r270 bottom locked value=0.47uF
C59 "C0402C104K8RACTU" 0402 2096.89,2533.65 r90 bottom locked value=0.1uF
C60 "GCM155C71A474KE36D" 0402L 1054.07,2547.61 r270 bottom locked value=0.47uF
C61 "C0402C104K8RACTU" 0402 2208.75,2356.78 r180 bottom locked value=0.1uF
C62 "C0402C104K8RACTU" 0402L 2065.16,2338.76 r180 bottom locked value=0.1uF
C63 "C0402C104K8RACTU" 0402L 2047.17,2155.5 r90 bottom locked value=0.1uF
C64 "C0402C104K8RACTU" 0402L 1318.67,2146.24 r270 bottom locked value=0.1uF
C65 "CC0402DRNPO9BN8R0" 0402L 2084.03,2014.98 r270 bottom locked value=8pF
C66 "CC0402DRNPO9BN8R0" 0402L 2084.03,1925.23 r90 bottom locked value=8pF
C67 "GCM155R71E103KA37D" 0402L 1302.54,1893.26 r0 bottom locked value=0.01uF
C68 "GCM155R71H104KE02D" 0402 319.58,1791.49 r0 bottom locked value=0.1uF
C69 "C0402C104K8RACTU" 0402L 2055.53,1796.75 r0 bottom locked value=0.1uF
C70 "GCM155R71E103KA37D" 0402L 1687.52,1752.97 r270 bottom locked value=0.01uF
C71 "C0402C104K8RACTU" 0402L 1623.51,1773.19 r0 bottom locked value=0.1uF
C72 "GCM155R71H104KE02D" 0402 1356.27,1735.95 r90 bottom locked value=0.1uF
C73 "GRT155C81A105KE01D" 0402L 1623.51,1739.69 r180 bottom locked value=1uF
C74 "C1608X7S1A475K080AC" 0603L 2174.28,1705.99 r0 bottom locked value=4.7uF
C75 "CL10B105KA8NNNC" 0603 1830.9,1685.69 r180 bottom locked
C76 "C0402C104K8RACTU" 0402 1129.1,1691.14 r180 bottom locked value=0.1uF
C77 "GCM155R71H104KE02D" 0402 2006.07,1673.9 r0 bottom locked value=0.1uF
C78 "GCM155R71H104KE02D" 0402 2174.46,1657.84 r0 bottom locked value=0.1uF
C79 "GCM1555C1H8R0DA16D" 0402L 2321.57,1579.73 r90 bottom locked
C80 "GCM155R71H104KE02D" 0402 1664.75,1580.58 r180 bottom locked value=0.1uF
C81 "GCM155R71H104KE02D" 0402 1664.9,1532.15 r180 bottom locked value=0.1uF
C82 "GCM1555C1H8R0DA16D" 0402L 2321.74,1496.66 r270 bottom locked
C83 "GCM155R71H104KE02D" 0402 2308.76,1410.7 r90 bottom locked value=0.1uF
C84 "C1608X7S1A475K080AC" 0603L 2358.23,1409.15 r270 bottom locked value=4.7uF
C85 "GCM155R71H104KE02D" 0402 2766.98,1329.68 r270 bottom locked value=0.1uF
C86 "GCM155R71H104KE02D" 0402 2308.76,1282.47 r90 bottom locked value=0.1uF
C87 "C1608X7S1A475K080AC" 0603L 2358.23,1280.18 r270 bottom locked value=4.7uF
C88 "GRM31CR70J226ME19K" FP-GRM31CR70J226ME19K_1206-MFG 1502.54,996.63 r90 bottom value=22µF
C89 "GCM155R71H104KE02D" 0402 1865.15,1042.92 r0 bottom locked value=0.1uF
C90 "CL10B105KA8NNNC" 0603 1859.24,984.52 r180 bottom locked
C91 "GCM155R71H104KE02D" 0402 2350.28,860.2 r0 bottom locked value=0.1uF
C92 "GRT155C71A225KE13D" FP-GRT155C71A225KE13D_0402-MFG 1688.95,530.54 r180 bottom locked value=2.2µF
C93 "GRT155C71A225KE13D" FP-GRT155C71A225KE13D_0402-MFG 1619.27,530.16 r180 bottom locked value=2.2µF
C94 "GRM31CR70J226ME19K" FP-GRM31CR70J226ME19K_1206-MFG 1278.4,509.39 r180 bottom locked value=22µF
C95 "GCM155R71H104KE02D" 0402 673.29,469.17 r180 bottom locked value=0.1uF
C96 "GCM155R71H104KE02D" 0402 1231.65,256.9 r0 bottom locked value=0.1uF
"CAUTION HOT SURFACE1" "CAUTION HOT SURFACE" IEC_HotSurface_Small 1934.52,815.43 r180 bottom
D1 "APHHS1005CGCK" APHHS1005_Green 325.14,2704.68 r0 top value=Green
D2 "APHHS1005CGCK" APHHS1005_Green 1272.34,2495.35 r0 top value=Green
D3 "PMEG3020EP,115" SOD-128 2565.53,1320.08 r90 top locked value=30V
D4 "TLMY1100-GS15" FP-TLMY1100-GS15_0603-MFG 1640.08,1182.23 r0 top
D5 "PMEG3020EP,115" SOD-128 2564.37,1044.79 r270 top locked value=30V
D6 "PMEG3020EP,115" SOD-128 1875.28,662.02 r270 top locked value=30V
D7 "SZP6SMB6.8AT3G" SMB 2550.83,692.23 r0 top locked value=5.8V
D8 "TLMY1000-GS08" TLMx1000_Yellow 714.19,568.15 r90 top locked value=Yellow
D9 "APHHS1005SURCK" APHHS1005_Red 2000.53,172.19 r90 top locked value=Red
F1 "32V, 5A" 1206 2493.3,539.23 r0 top locked
FB1 "BLM21PG300SH1D" 0805_HV 2019.58,628.43 r180 top locked value="30 ohm"
FB2 "BLM21PG300SH1D" 0805_HV 2020.28,540.06 r180 top locked value="30 ohm"
FID1 "Fiducial" Fiducial10-20 64.52,3265.39 r0 top locked
FID2 "Fiducial" Fiducial10-20 64.52,110.99 r90 top locked
FID2_1 "Fiducial" Fiducial10-20 364.78,-125.73 r90 top locked
FID2_1_1 "Fiducial" Fiducial10-20 2666.72,-125.73 r270 top locked
FID2_1_2 "Fiducial" Fiducial10-20 2666.7,3724.51 r270 top locked
FID2_1_3 "Fiducial" Fiducial10-20 364.77,3724.51 r90 top locked
FID3 "Fiducial" Fiducial10-20 2272.31,108.09 r0 top locked
FID5 "Fiducial" Fiducial10-20 64.52,110.99 r90 bottom
FID5_1 "Fiducial" Fiducial10-20 364.78,-125.73 r90 bottom locked
FID5_1_1 "Fiducial" Fiducial10-20 2666.72,-125.73 r270 bottom locked
FID5_1_2 "Fiducial" Fiducial10-20 2666.7,3724.51 r270 bottom locked
FID5_1_3 "Fiducial" Fiducial10-20 364.77,3724.51 r90 bottom locked
FID6 "Fiducial" Fiducial10-20 2272.31,108.09 r90 bottom locked
FID7 "Fiducial" Fiducial10-20 64.52,3265.39 r90 bottom
J1 "SOLDER JUMPER" SolderJumper 2716.19,2483.87 r270 top locked
J2 "SOLDER JUMPER" SolderJumper 2722.11,2221.14 r90 top locked
J3 "SOLDER JUMPER" SolderJumper 2722.11,1956.39 r270 top locked
J4 "SOLDER JUMPER" SolderJumper 2730.38,1699.05 r90 top locked
J5 "105017-0001" CONN_105017-0001 2921.25,1364.26 r90 top
J6 "QSH-030-01-L-D-A" Samtec_QSH-030-01-X-D-A 481.52,921 r0 top locked
J7 "105017-0001" CONN_105017-0001 2921.25,863.74 r90 top
J8 "PJ-002AH" CUI_PJ-002AH 2748.01,363.49 r0 top locked
J9 "SOLDER JUMPER" SolderJumper 2162.29,270.16 r180 top locked
J10 "SOLDER JUMPER" SolderJumper 868.65,166.39 r0 top locked
J11 "SOLDER JUMPER" SolderJumper 1546.89,155.44 r0 top locked
J12 "TSW-102-08-G-S-RA" TSW-102-08-G-S-RA 2871.47,2755.79 r270 bottom locked
J13 "0022288072" FP-0022288072_HDR7-MFG 49,2490.39 r270 bottom locked
J14 "SSM-110-S-DV" Samtec_SSM-110-x-DV 850.23,2137.22 r270 bottom locked
J15 "SSM-110-S-DV" Samtec_SSM-110-x-DV 2550.23,2137.22 r270 bottom locked
J16 "TSW-102-08-G-S-RA" TSW-102-08-G-S-RA 2871.42,2496.58 r270 bottom locked
J17 "TSW-102-08-G-S-RA" TSW-102-08-G-S-RA 2871.42,2237.36 r270 bottom locked
J18 "TSW-102-08-G-S-RA" TSW-102-08-G-S-RA 2871.42,1978.15 r270 bottom locked
J19 "M50-3930342" FP-M50-3930342_HDR3-MFG 23.62,1994.72 r90 bottom locked
J20 "TSW-102-08-G-S-RA" TSW-102-08-G-S-RA 2871.44,1718.94 r270 bottom locked
J21 "61300411021" Wurth_61300411021 158.04,1270.16 r90 bottom locked
J22 "TSW-102-08-G-S-RA" TSW-102-08-G-S-RA 158.99,903.83 r90 bottom locked
J23 "TSW-102-08-G-S-RA" TSW-102-08-G-S-RA 158.99,629.15 r90 bottom locked
J24 "TSW-102-08-G-S-RA" TSW-102-08-G-S-RA 158.99,373.6 r90 bottom locked
L1 "BLM21PG300SH1D" 0805 2674.07,1343.74 r90 top locked value="30 ohm"
L2 "DFE201612PD-R15M=P2" "FP-DFE201612PD-R15M=P2_0806 (2016)-MFG" 1416.31,1128.09 r180 top locked value=0.15uH
L3 "DFE201210U-R47M=P2" "FP-DFE201210U-R47M=P2_0805 (2012)-MFG" 1713.89,983.51 r90 top locked value=0.47uH
L4 "BLM21PG300SH1D" 0805 2669.51,910.41 r90 top locked value="30 ohm"
L5 "DFE201210U-R47M=P2" "FP-DFE201210U-R47M=P2_0805 (2012)-MFG" 1293.67,709.54 r180 top locked value=0.47uH
L6 "DFE201612PD-R15M=P2" "FP-DFE201612PD-R15M=P2_0806 (2016)-MFG" 1143.35,485.52 r180 top value=0.15uH
L7 "BLM15PD300SZ1D" 0402L 308,334.01 r0 top locked
L8 "BLM15HG601SN1D" 0402L 2420.4,1436.22 r180 bottom locked value="600 ohm"
L9 "BLM15HG601SN1D" 0402L 2466.83,1386.66 r180 bottom locked value="600 ohm"
L10 "BLM15HG601SN1D" 0402L 2420.4,1307.74 r180 bottom locked value="600 ohm"
LBL1 "THT-14-423-10" Label_650x200 1062.31,871.09 r0 bottom
Logo1 "Texas Instruments" TI_Stacked_Overlay_Small 1816.31,2539.09 r0 top
Logo2 "WEEE logo" WEEE_Minimum 2120.31,2346.09 r0 top
LOGO3 "FCC disclaimer" FCC_disclaimer 899.12,3533.72 r180 bottom (schematic designator Logo3)
Logo4 "CE Mark" CE_Mark_5mm 2148.64,480.77 r180 bottom
Q1 "BSS123W-7-F" SOT-323 309.53,2797.04 r270 bottom locked value=100V
Q2 "BSS123W-7-F" SOT-323 1264.99,2632.21 r180 bottom locked value=100V
Q3 "BSS123W-7-F" SOT-323 710.09,570.11 r90 bottom locked value=100V
R1 "CRCW040210K0FKED" 0402L 1785.53,2767.81 r0 top locked value=10.0k
R2 "CRCW040210K0FKED" 0402L 1838.44,2701.42 r90 top locked value=10.0k
R3 "CRCW040210K0FKED" 0402L 272.84,2662.39 r0 top locked value=10.0k
R4 "CRCW040210K0FKED" 0402L 371.62,2661.75 r0 top locked value=10.0k
R5 "CRCW040210K0FKED" 0402L 1986.29,2315.8 r90 top locked value=10.0k
R6 "ERJ-2GE0R00X" FP-ERJ-2GE0R00X_0402-MFG 295.02,2318.24 r270 top locked value=0
R7 "ERJ-2GE0R00X" FP-ERJ-2GE0R00X_0402-MFG 243.74,2314.9 r270 top locked value=0
R8 "CRCW040210K0FKED" 0402L 364.07,2327.22 r0 top locked value=10.0k
R9 "ERJ-2GE0R00X" FP-ERJ-2GE0R00X_0402-MFG 2301.63,2299.12 r90 top locked value=0
R10 "CRCW040210K0FKED" 0402L 364.07,2287.35 r180 top locked value=10.0k
R11 "CRCW040210K0FKED" 0402L 249.33,2208.81 r90 top locked value=10.0k
R12 "CRCW040210K0FKED" 0402L 297.37,2208.81 r90 top locked value=10.0k
R13 "CRCW0402100KFKED" 0402 638.39,2183.31 r180 top value=100k
R14 "CRCW0402100KFKEDC" FP-CRCW0402100KFKEDC_0402-IPC_B 1054.07,2149.73 r0 top locked value=100k
R15 "ERJ-2GE0R00X" FP-ERJ-2GE0R00X_0402-MFG 452.45,2146.71 r0 top locked value=0
R16 "ERJ-2GE0R00X" FP-ERJ-2GE0R00X_0402-MFG 632.41,2128.4 r180 top locked value=0
R17 "ERJ-2GE0R00X" FP-ERJ-2GE0R00X_0402-MFG 563.03,2128.25 r180 top locked value=0
R18 "WSL080500000ZEA9" FP-WSL080500000ZEA9_0805-MFG 2651.22,2103.2 r0 top locked value=0
R19 "CRCW0402100KFKEDC" FP-CRCW0402100KFKEDC_0402-IPC_B 1054.18,2096.32 r180 top locked value=100k
R20 "ERJ-2GE0R00X" FP-ERJ-2GE0R00X_0402-MFG 498.08,2081.48 r90 top locked value=0
R21 "CRCW040261R9FKED" 0402L 145.33,2040.39 r90 top locked value=61.9
R22 "CRCW04021K00FKED" 0402L 1564.9,2054.43 r0 top locked value=1.00k
R23 "CRCW040210K0FKED" 0402L 1055.25,2050.45 r180 top locked value=10.0k
R24 "CRCW040261R9FKED" 0402L 145.33,1951.02 r90 top locked value=61.9
R25 "CRCW040210K0FKED" 0402L 945.47,1930.78 r0 top value=10.0k
R26 "CRCW040233R2FKED" 0402 1952.84,1692.75 r90 top locked value=33.2
R27 "CRCW040233R2FKED" 0402 1900.18,1692.38 r90 top locked value=33.2
R28 "MCT06030Z0000ZP500" 0603 615.94,1690.7 r0 top locked value=0
R29 "CRCW040210K0FKED" 0402L 266.66,1686.28 r180 top locked value=10.0k
R30 "CRCW04022K20JNED" 0402L 2272.89,1635.53 r90 top locked value=2.2k
R31 "CRCW0402750RFKED" 0402L 266.39,1648.29 r180 top locked value=750
R32 "ERJ-2GE0R00X" FP-ERJ-2GE0R00X_0402-MFG 261.32,1594.35 r90 top locked value=0
R33 "CRCW040210K0FKED" 0402L 2074.71,1526.33 r270 top locked value=10.0k
R34 "CRCW040210K0FKED" 0402L 2180.44,1443.28 r270 top locked value=10.0k
R35 "CRCW040210K0FKED" 0402L 2231.41,1441.59 r270 top locked value=10.0k
R36 "CRCW0402100KFKED" 0402 2065.54,1382.26 r90 top locked value=100k
R37 "MCT06030Z0000ZP500" 0603 412.45,1399.27 r180 top locked value=0
R38 "CRCW040210K0FKED" 0402L 2178.64,1361.9 r90 top locked value=10.0k
R39 "ERJ-2GE0R00X" FP-ERJ-2GE0R00X_0402-MFG 1977.34,1301.64 r90 top locked value=0
R40 "ERJ-2GE0R00X" FP-ERJ-2GE0R00X_0402-MFG 1927.81,1301.42 r90 top locked value=0
R41 "CRCW040233R2FKED" 0402 2071.58,1276.37 r90 top locked value=33.2
R42 "ERJ-2GE0R00X" FP-ERJ-2GE0R00X_0402-MFG 2024.65,1291.67 r90 top locked value=0
R43 "MCT06030Z0000ZP500" 0603 1189.58,1273.69 r180 top locked value=0
R44 "CRCW040233R2FKED" 0402 2127.33,1242.16 r90 top locked value=33.2
R45 "ERJ-2GE0R00X" FP-ERJ-2GE0R00X_0402-MFG 657.27,1264.03 r90 top locked value=0
R46 "ERJ-2GE0R00X" FP-ERJ-2GE0R00X_0402-MFG 702.06,1264.03 r90 top locked value=0
R47 "ERJ-2GE0R00X" FP-ERJ-2GE0R00X_0402-MFG 1768.01,1219.68 r0 top value=0
R48 "CRCW040233R2FKED" 0402 2189.75,1172.27 r90 top locked value=33.2
R49 "ERJ-2GE0R00X" FP-ERJ-2GE0R00X_0402-MFG 254.59,1176.28 r0 top locked value=0
R50 "ERJ-2GE0R00X" FP-ERJ-2GE0R00X_0402-MFG 730.23,1171.07 r90 top locked value=0
R51 "ERJ-2GE0R00X" FP-ERJ-2GE0R00X_0402-MFG 1785.48,1159.27 r90 top locked value=0
R52 "ERJ-2GE0R00X" FP-ERJ-2GE0R00X_0402-MFG 1995.66,1151.06 r180 top locked value=0
R53 "ERJ-2GE0R00X" FP-ERJ-2GE0R00X_0402-MFG 1884.81,1135.33 r270 top locked value=0
R54 "ERJ-2GE0R00X" FP-ERJ-2GE0R00X_0402-MFG 1838.78,1134.9 r270 top locked value=0
R55 "ERJ-2GE0R00X" FP-ERJ-2GE0R00X_0402-MFG 1933.91,1134.81 r270 top locked value=0
R56 "ERJ-2GE0R00X" FP-ERJ-2GE0R00X_0402-MFG 254.43,1120.2 r0 top locked value=0
R57 "ERJ-2GE0R00X" FP-ERJ-2GE0R00X_0402-MFG 719.84,1108.93 r0 top locked value=0
R58 "ERJ-2GE0R00X" FP-ERJ-2GE0R00X_0402-MFG 254.43,1075.49 r0 top locked value=0
R59 "ERJ-2GE0R00X" FP-ERJ-2GE0R00X_0402-MFG 719.3,1069.85 r0 top locked value=0
R60 "MCT06030Z0000ZP500" 0603 2726.62,1052.4 r180 top locked value=0
R61 "ERJ-2GE0R00X" FP-ERJ-2GE0R00X_0402-MFG 254.43,1035.04 r0 top locked value=0
R62 "ERJ-2GE0R00X" FP-ERJ-2GE0R00X_0402-MFG 254.43,993.83 r0 top locked value=0
R63 "CRCW040210K0FKED" 0402L 2735.45,1004.53 r0 top locked value=10.0k
R64 "ERJ-2GE0R00X" FP-ERJ-2GE0R00X_0402-MFG 717.52,975.34 r0 top value=0
R65 "CRCW040210K0FKED" 0402L 2146.86,943.16 r90 top locked value=10.0k
R66 "ERJ-2GE0R00X" FP-ERJ-2GE0R00X_0402-MFG 717.52,945.34 r0 top value=0
R67 "ERJ-2GE0R00X" FP-ERJ-2GE0R00X_0402-MFG 805.94,916.96 r0 top value=0
R68 "ERJ-2GE0R00X" FP-ERJ-2GE0R00X_0402-MFG 805.94,886.96 r0 top value=0
R69 "ERJ-2GE0R00X" FP-ERJ-2GE0R00X_0402-MFG 717.52,859.41 r0 top value=0
R70 "CRCW040218K0FKED" 0402L 1793.3,845.6 r270 top locked value=18.0k
R71 "ERJ-2GE0R00X" FP-ERJ-2GE0R00X_0402-MFG 717.52,825.41 r0 top value=0
R72 "CRCW0402100KFKEDC" FP-CRCW0402100KFKEDC_0402-IPC_B 2075.16,799.35 r180 top locked value=100k
R73 "ERJ-2GE0R00X" FP-ERJ-2GE0R00X_0402-MFG 805.94,798.2 r0 top value=0
R74 "ERJ-2GE0R00X" FP-ERJ-2GE0R00X_0402-MFG 1278.6,790.55 r90 top locked value=0
R75 "CRCW0402100KFKEDC" FP-CRCW0402100KFKEDC_0402-IPC_B 1337.07,787.16 r90 top locked value=100k
R76 "CRCW040218K0FKED" 0402L 1442.58,799.7 r0 top locked value=18.0k
R77 "CRCW040210K0FKED" 0402L 2001.81,797.65 r0 top locked value=10.0k
R78 "ERJ-2GE0R00X" FP-ERJ-2GE0R00X_0402-MFG 805.94,768.2 r0 top value=0
R79 "CRCW0402100KFKEDC" FP-CRCW0402100KFKEDC_0402-IPC_B 1727.69,764.37 r0 top locked value=100k
R80 "ERJ-2GE0R00X" FP-ERJ-2GE0R00X_0402-MFG 264.27,752.08 r0 top locked value=0
R81 "ERJ-2GE0R00X" FP-ERJ-2GE0R00X_0402-MFG 717.52,739.15 r0 top value=0
R82 "ERJ-2GE0R00X" FP-ERJ-2GE0R00X_0402-MFG 264.27,713.22 r0 top locked value=0
R83 "ERJ-2GE0R00X" FP-ERJ-2GE0R00X_0402-MFG 717.52,709.15 r0 top value=0
R84 "CRCW04023K32FKED" 0402 1727.97,709.1 r0 top locked value=3.32k
R85 "ERJ-2GE0R00X" FP-ERJ-2GE0R00X_0402-MFG 805.94,680.09 r0 top value=0
R86 "ERJ-2GE0R00X" FP-ERJ-2GE0R00X_0402-MFG 264.27,674.23 r0 top locked value=0
R87 "ERJ-2GE0R00X" FP-ERJ-2GE0R00X_0402-MFG 805.94,650.09 r0 top value=0
R88 "ERJ-2GEJ511X" 0402L 668.94,562.86 r90 top locked value=510
R89 "ERJ-2GE0R00X" FP-ERJ-2GE0R00X_0402-MFG 257.26,531.55 r90 top locked value=0
R90 "ERJ-2GE0R00X" FP-ERJ-2GE0R00X_0402-MFG 300.86,531.55 r90 top locked value=0
R91 "OAR3R010FLF" FP-OAR3R010FLF_RADIAL-MFG 2148.64,390.39 r180 top locked value=10m
R92 "MCT06030Z0000ZP500" 0603 319.2,400.57 r0 top locked value=0
R93 "ERJ-2GEJ511X" 0402L 1951.09,174.16 r90 top locked value=510
R94 "OAR3R010FLF" FP-OAR3R010FLF_RADIAL-MFG 747.49,166.61 r0 top locked value=10m
R95 "OAR3R010FLF" FP-OAR3R010FLF_RADIAL-MFG 1505.59,166.11 r0 top locked value=10m
R96 "ERJ-2GEJ511X" 0402L 231.93,2816.77 r270 bottom locked value=510
R97 "ERJ-2GE0R00X" FP-ERJ-2GE0R00X_0402-MFG 1920.22,2789.54 r0 bottom locked value=0
R98 "ERJ-2GE0R00X" FP-ERJ-2GE0R00X_0402-MFG 1372.76,2784.94 r180 bottom locked value=0
R99 "CRCW040282K5FKED" 0402L 1235.04,2750.96 r270 bottom locked value=82.5k
R100 "CRCW0402750RFKED" 0402L 1269.86,2750.91 r270 bottom locked value=750
R101 "CRCW04027K87FKED" 0402L 1201.44,2750.52 r90 bottom locked value=7.87k
R102 "ERJ-2GE0R00X" FP-ERJ-2GE0R00X_0402-MFG 1365.87,2722.01 r0 bottom locked value=0
R103 "ERJ-2GE0R00X" FP-ERJ-2GE0R00X_0402-MFG 2263.32,2694.37 r90 bottom locked value=0
R104 "ERJ-2GE0R00X" FP-ERJ-2GE0R00X_0402-MFG 2205.72,2694.37 r90 bottom locked value=0
R105 "CRCW040210K0FKED" 0402L 1545.58,2706.15 r180 bottom locked value=10.0k
R106 "CRCW040210K0FKED" 0402L 1294.95,2696.32 r180 bottom locked value=10.0k
R107 "ERJ-2GEJ511X" 0402L 292.04,2669.53 r0 bottom locked value=510
R108 "CRCW040210K0FKED" 0402L 2114.26,2646.91 r90 bottom locked value=10.0k
R109 "ERJ-2GEJ511X" 0402L 1348.02,2644.87 r270 bottom locked value=510
R110 "ERJ-2GE0R00X" FP-ERJ-2GE0R00X_0402-MFG 1813.02,2647.3 r180 bottom locked value=0
R111 "ERJ-2GE0R00X" FP-ERJ-2GE0R00X_0402-MFG 2345.48,2587.21 r0 bottom locked value=0
R112 "CRCW040233R2FKED" 0402 1616.86,2553.51 r90 bottom locked value=33.2
R113 "CRCW040233R2FKED" 0402 1566.92,2553.21 r90 bottom locked value=33.2
R114 "CRCW040233R2FKED" 0402 1518.21,2552.2 r90 bottom locked value=33.2
R115 "CRCW040233R2FKED" 0402 1470.11,2552.2 r90 bottom locked value=33.2
R116 "MCT06030Z0000ZP500" 0603 1102.94,2535.8 r90 bottom locked value=0
R117 "ERJ-2GE0R00X" FP-ERJ-2GE0R00X_0402-MFG 1719.52,2553.9 r270 bottom locked value=0
R118 "ERJ-2GE0R00X" FP-ERJ-2GE0R00X_0402-MFG 1669.81,2553.52 r270 bottom locked value=0
R119 "CRCW04021K00FKED" 0402L 1882.99,2540.92 r90 bottom locked value=1.00k
R120 "CRCW04021K00FKED" 0402L 1915.24,2540.55 r90 bottom locked value=1.00k
R121 "CRCW04021K00FKED" 0402L 1947.45,2540.35 r90 bottom locked value=1.00k
R122 "CRCW04021K00FKED" 0402L 1848.12,2540.14 r90 bottom locked value=1.00k
R123 "CRCW04024K87FKED" 0402L 1813.42,2540.03 r270 bottom locked value=4.87k
R124 "ERJ-2GE0R00X" FP-ERJ-2GE0R00X_0402-MFG 1422.04,2528.51 r90 bottom locked value=0
R125 "ERJ-2GE0R00X" FP-ERJ-2GE0R00X_0402-MFG 1371.68,2527.14 r90 bottom locked value=0
R126 "ERJ-2GE0R00X" FP-ERJ-2GE0R00X_0402-MFG 2346.59,2487.22 r0 bottom locked value=0
R127 "ERJ-2GE0R00X" FP-ERJ-2GE0R00X_0402-MFG 2762.19,2486.67 r0 bottom locked value=0
R128 "ERJ-2GEJ511X" 0402L 1251.52,2460.2 r270 bottom locked value=510
R129 "ERJ-2GE0R00X" FP-ERJ-2GE0R00X_0402-MFG 2225.07,2441.07 r270 bottom locked value=0
R130 "ERJ-2GE0R00X" FP-ERJ-2GE0R00X_0402-MFG 2280.17,2440.28 r270 bottom locked value=0
R131 "CRCW04024K70JNED" 0402 2102.79,2442.26 r0 bottom locked value=4.7k
R132 "ERJ-2GE0R00X" FP-ERJ-2GE0R00X_0402-MFG 2358.64,2407.39 r270 bottom locked value=0
R133 "ERJ-2GE0R00X" FP-ERJ-2GE0R00X_0402-MFG 2762.19,2387.08 r0 bottom locked value=0
R134 "ERJ-2GE0R00X" FP-ERJ-2GE0R00X_0402-MFG 649.86,2386.52 r0 bottom locked value=0
R135 "CRCW040249R9FKED" 0402L 2063.98,2373.28 r180 bottom locked value=49.9
R136 "CRCW040210K0FKED" 0402L 1278.8,2334.18 r0 bottom locked value=10.0k
R137 "ERJ-2GE0R00X" FP-ERJ-2GE0R00X_0402-MFG 2137.44,2312.54 r90 bottom locked value=0
R138 "ERJ-2GE0R00X" FP-ERJ-2GE0R00X_0402-MFG 2360.37,2307.39 r270 bottom locked value=0
R139 "ERJ-2GE0R00X" FP-ERJ-2GE0R00X_0402-MFG 1278.96,2291.52 r180 bottom locked value=0
R140 "ERJ-2GE0R00X" FP-ERJ-2GE0R00X_0402-MFG 2765.21,2289.32 r0 bottom locked value=0
R141 "ERJ-2GE0R00X" FP-ERJ-2GE0R00X_0402-MFG 649.86,2287.98 r0 bottom locked value=0
R142 "ERJ-2GE0R00X" FP-ERJ-2GE0R00X_0402-MFG 1278.29,2242.72 r180 bottom locked value=0
R143 "CRCW040210K0FKED" 0402L 1218.51,2159.57 r90 bottom locked value=10.0k
R144 "CRCW040210K0FKED" 0402L 2139.97,2139.99 r90 bottom locked value=10.0k
R145 "MCT06030Z0000ZP500" 0603 1270.05,2094.12 r90 bottom locked value=0
R146 "ERJ-2GE0R00X" FP-ERJ-2GE0R00X_0402-MFG 2354.21,2110.01 r270 bottom locked value=0
R147 "ERJ-2GE0R00X" FP-ERJ-2GE0R00X_0402-MFG 2771.11,2086.46 r0 bottom locked value=0
R148 "ERJ-2GE0R00X" FP-ERJ-2GE0R00X_0402-MFG 2359.24,2008.57 r270 bottom locked value=0
R149 "CRCW040210K0FKED" 0402L 1224.1,2002.52 r0 bottom locked value=10.0k
R150 "ERJ-2GE0R00X" FP-ERJ-2GE0R00X_0402-MFG 2777.02,1987.21 r0 bottom locked value=0
R151 "ERJ-2GE0R00X" FP-ERJ-2GE0R00X_0402-MFG 645.75,1967.07 r90 bottom locked value=0
R152 "CRCW040210K0FKED" 0402L 261.67,1960.2 r180 bottom locked value=10.0k
R153 "CRCW0402330KFKED" 0402L 1302.72,1956.64 r180 bottom locked value=330k
R154 "CRCW0402330KFKED" 0402L 1302.38,1925.23 r0 bottom locked value=330k
R155 "ERJ-2GE0R00X" FP-ERJ-2GE0R00X_0402-MFG 506.32,1909.78 r270 bottom locked value=0
R156 "ERJ-2GE0R00X" FP-ERJ-2GE0R00X_0402-MFG 2356.43,1909.61 r270 bottom locked value=0
R157 "CRCW040210K0FKED" 0402L 261.32,1922.72 r0 bottom locked value=10.0k
R158 "ERJ-2GE0R00X" FP-ERJ-2GE0R00X_0402-MFG 2740.23,1870.94 r270 bottom locked value=0
R159 "CRCW0402100KFKED" 0402L 2778.51,1832.81 r270 bottom locked value=100k
R160 "ERJ-2GE0R00X" FP-ERJ-2GE0R00X_0402-MFG 2063.98,1836.89 r180 bottom locked value=0
R161 "CRCW040210K0FKED" 0402L 587.11,1824.45 r180 bottom locked value=10.0k
R162 "ERJ-2GE0R00X" FP-ERJ-2GE0R00X_0402-MFG 651.56,1805.78 r270 bottom locked value=0
R163 "ERJ-2GE0R00X" FP-ERJ-2GE0R00X_0402-MFG 2339.53,1787.22 r0 bottom locked value=0
R164 "ERJ-2GE0R00X" FP-ERJ-2GE0R00X_0402-MFG 1058.83,1780.72 r90 bottom locked value=0
R165 "CRCW04027K87FKED" 0402L 185.74,1742.05 r270 bottom locked value=7.87k
R166 "ERJ-2GEJ101X" 0402L 2055.25,1763.23 r0 bottom locked value=100
R167 "CRCW040210K0FKED" 0402L 295.22,1732.95 r270 bottom locked value=10.0k
R168 "ERJ-2GE0R00X" FP-ERJ-2GE0R00X_0402-MFG 1296.07,1730.85 r90 bottom locked value=0
R169 "ERJ-2GE0R00X" FP-ERJ-2GE0R00X_0402-MFG 1405.42,1716.84 r90 bottom locked value=0
R170 "ERJ-2GE0R00X" FP-ERJ-2GE0R00X_0402-MFG 1923.81,1699.05 r90 bottom locked value=0
R171 "ERJ-2GE0R00X" FP-ERJ-2GE0R00X_0402-MFG 1224.73,1696.9 r0 bottom locked value=0
R172 "ERJ-2GE0R00X" FP-ERJ-2GE0R00X_0402-MFG 637.98,1687.88 r0 bottom locked value=0
R173 "ERJ-2GE0R00X" FP-ERJ-2GE0R00X_0402-MFG 2336.31,1687.21 r0 bottom locked value=0
R174 "ERJ-2GE0R00X" FP-ERJ-2GE0R00X_0402-MFG 1454.61,1668.22 r90 bottom locked value=0
R175 "CRCW040210K0FKED" 0402L 598.67,1642.87 r180 bottom locked value=10.0k
R176 "CRCW04028K87FKED" 0402 233.75,1558.61 r90 bottom locked value=8.87k
R177 "CRCW040210K0FKED" 0402L 1463.38,1531.27 r180 bottom locked value=10.0k
R178 "ERJ-2GE0R00X" FP-ERJ-2GE0R00X_0402-MFG 1665.79,1481.37 r180 bottom locked value=0
R179 "CRCW0402100KFKEDC" FP-CRCW0402100KFKEDC_0402-IPC_B 1459.49,1432.5 r180 bottom locked value=100k
R180 "ERJ-2GE0R00X" FP-ERJ-2GE0R00X_0402-MFG 1665.17,1432.23 r180 bottom locked value=0
R181 "CRCW0402100KFKEDC" FP-CRCW0402100KFKEDC_0402-IPC_B 1388.79,1412.99 r270 bottom locked value=100k
R182 "CRCW040210K0FKED" 0402L 1290.96,1399.27 r270 bottom locked value=10.0k
R183 "CRCW040230K0FKED" 0402L 2690.56,1380.6 r0 bottom locked value=30.0k
R184 "ERJ-2GE0R00X" 0402 1646.88,1343.83 r0 bottom locked value=0
R185 "ERJ-2GE0R00X" FP-ERJ-2GE0R00X_0402-MFG 2696.11,1301.42 r270 bottom locked value=0
R186 "ERJ-2GE0R00X" 0402 1548.11,1274.3 r0 bottom locked value=0
R187 "CRCW040233R2FKED" 0402 1655.05,1264.59 r180 bottom locked value=33.2
R188 "ERJ-2GEJ511X" 0402L 1643.84,1224.3 r0 bottom locked value=510
R189 "ERJ-2RKF1001X" 0402 2335.3,1204.09 r180 bottom locked value=1.00k
R190 "CRCW040233R2FKED" 0402 2336,1154.03 r0 bottom locked value=33.2
R191 "CRCW040210K0FKED" 0402L 2452.96,1087.16 r180 bottom locked value=10.0k
R192 "WSL1206R0200FEB" FP-WSL1206R0200FEB_1206-MFG 2188.17,962.61 r270 bottom locked value=20m
R193 "CRCW040210K0FKED" 0402L 2552.93,1030.57 r180 bottom locked value=10.0k
R194 "CRCW040210K0FKED" 0402L 2552.38,997.38 r0 bottom locked value=10.0k
R195 "CRCW040210K0FKED" 0402L 2551.81,963.55 r0 bottom locked value=10.0k
R196 "CRCW040210K0FKED" 0402L 2551.07,930.88 r180 bottom locked value=10.0k
R197 "ERJ-2GE0R00X" FP-ERJ-2GE0R00X_0402-MFG 2554.2,890.28 r0 bottom locked value=0
R198 "ERJ-2GE0R00X" FP-ERJ-2GE0R00X_0402-MFG 2454.22,857.02 r0 bottom locked value=0
R199 "CRCW04023K32FKED" 0402 1423.29,678.79 r90 bottom locked value=3.32k
R200 "CRCW0402100KFKEDC" FP-CRCW0402100KFKEDC_0402-IPC_B 1475.31,687.88 r90 bottom locked value=100k
R201 "CRCW0402100KFKED" 0402 820.75,653.22 r180 bottom locked value=100k
R202 "CRCW040210K0FKED" 0402L 815.42,610.79 r0 bottom locked value=10.0k
R203 "ERJ-2GEJ511X" 0402L 795.54,553.1 r270 bottom locked value=510
R204 "ERJ-2GE0R00X" FP-ERJ-2GE0R00X_0402-MFG 569.46,469.17 r180 bottom locked value=0
R205 "WSL1206R0200FEB" FP-WSL1206R0200FEB_1206-MFG 1069.44,377.49 r270 bottom locked value=20m
R206 "CRCW040210K0FKED" 0402L 1280.29,455.23 r0 bottom locked value=10.0k
R207 "CRCW040210K0FKED" 0402L 1434.2,445.45 r180 bottom locked value=10.0k
R208 "WSL1206R0200FEB" FP-WSL1206R0200FEB_1206-MFG 835.51,348.57 r270 bottom locked value=20m
R209 "ERJ-2GE0R00X" FP-ERJ-2GE0R00X_0402-MFG 469.47,420.9 r180 bottom locked value=0
R210 "CRCW040210K0FKED" 0402L 1433.65,412.26 r0 bottom locked value=10.0k
R211 "CRCW040210K0FKED" 0402L 472.61,380.3 r0 bottom locked value=10.0k
R212 "CRCW040210K0FKED" 0402L 1433.08,378.43 r0 bottom locked value=10.0k
R213 "CRCW0402100KFKED" 0402 1597.77,361.34 r180 bottom locked value=100k
R214 "CRCW040210K0FKED" 0402L 1683.05,332.56 r90 bottom locked value=10.0k
R215 "CRCW040210K0FKED" 0402L 471.87,347.64 r180 bottom locked value=10.0k
R216 "CRCW040210K0FKED" 0402L 1432.34,345.76 r180 bottom locked value=10.0k
R217 "ERJ-2GE0R00X" FP-ERJ-2GE0R00X_0402-MFG 1601.22,309.52 r0 bottom locked value=0
R218 "ERJ-2GE0R00X" FP-ERJ-2GE0R00X_0402-MFG 1435.47,305.16 r0 bottom locked value=0
R219 "CRCW040210K0FKED" 0402L 471.3,313.8 r180 bottom locked value=10.0k
R220 "CRCW040210K0FKED" 0402L 470.75,280.61 r0 bottom locked value=10.0k
R221 "CRCW040210K0FKED" 0402L 624.66,270.83 r180 bottom locked value=10.0k
R222 "ERJ-2GE0R00X" FP-ERJ-2GE0R00X_0402-MFG 1335.49,256.9 r0 bottom locked value=0
S1 "218-8LPST" SW_218-8LP 1604.28,1821.68 r270 top locked
S2 "PTS645SM43SMTR92 LFS" SW_PTS645SM43SMT 426.46,1684.66 r270 top locked
S3 "218-2LPST" SW_218-2LP 1628.09,1315.87 r0 top locked
SW1 "AYZ0102AGRLC" FP-AYZ0102AGRLC_SMT_SW_7MM2_5MM3-MFG 68.14,1665.84 r270 top locked
TP1 "TESTPOINT" TP_25MIL-SMT 1462.02,2715.86 r180 top locked
TP2 "TESTPOINT" TP_25MIL-SMT 1334.73,2365.09 r0 top locked
TP3 "TESTPOINT" TP_25MIL-SMT 1224.1,2193.24 r0 top locked
TP4 "TESTPOINT" TP_25MIL-SMT 1038.08,1963.33 r90 top locked
TP5 "TESTPOINT" TP_25MIL-SMT 2190.81,944.83 r0 top locked
TP6 "TESTPOINT" TP_25MIL-SMT 1911.68,820.76 r180 top locked
TP7 "TESTPOINT" TP_VIA_060RND040 2796.2,634.06 r180 top locked
TP8 "TESTPOINT" TP_25MIL-SMT 1744.12,490.77 r270 top locked
U1 "IWRL6432WMOD" MBB0030A-MFG 1515.73,3261.61 r270 top locked
U2 "SN74LVC1G11DSFR" DSF0006A 1748.03,2720.77 r180 top locked
U3 "CAT24C08WI-GT3" SOIC-8 319.65,2493.87 r270 top locked
U4 "TPS78417QDBVRQ1" DBV0005A-MFG 582.13,2294.91 r90 top locked
U5 "LM4040C25QDBZR" DBZ0003A_N 1582.61,2154.65 r90 top locked
U6 "TS3A27518ETRTWRQ1" RTW0024B-MFG 880.73,2047.57 r270 top locked
U7 "TCAN3403DRQ1" D0008B-MFG 329.92,1995.7 r180 top locked
U8 "93LC46B-I/ST" TSSOP-8 2183.66,1638.24 r90 top locked
U9 "SN65LVDS31MDREP" D0016A_N 925.64,1503.5 r90 top locked
U10 "TPD4E004DRYR" DRY0006A 2772.8,1370.01 r180 top locked
U11 "SN65LVDS31MDREP" D0016A_N 1065.2,942.07 r0 top locked
U12 "TPS2116DRLR" DRL0008A-MFG 2051.35,880.27 r0 top locked
U13 "TPS6285020MQDRLRQ1" DRL0008A-MFG 1724.68,861.81 r90 top locked
U14 "TPD4E004DRYR" DRY0006A 2771.82,869.49 r0 top locked
U15 "TPS6285021HQDRLRQ1" DRL0008A-MFG 1413.96,726 r180 top locked
U16 "TS5A23157QDGSRQ1" DGS0010A_N 1743.51,2731.78 r0 bottom locked
U17 "SN3257QDYYRQ1" DYY0016A 2215.22,2567.61 r270 bottom locked
U18 "TM4C1294NCPDTT3" PDT0128A 1685.13,2140.54 r0 bottom locked
U19 "TS5A23157QDGSRQ1" DGS0010A_N 2231.26,2205.48 r90 bottom locked
U20 "TS5A23157QDGSRQ1" DGS0010A_N 1161.85,1850.83 r270 bottom locked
